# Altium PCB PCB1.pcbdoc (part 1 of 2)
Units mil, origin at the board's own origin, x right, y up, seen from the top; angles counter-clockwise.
Board outline 3543.4 x 3543.1 mil, 4 copper layers (Top Layer, Inner1, Inner2, Bottom Layer), stack 62.5 mil thick; 107 components, 108 nets, 595 pads, 260 vias.
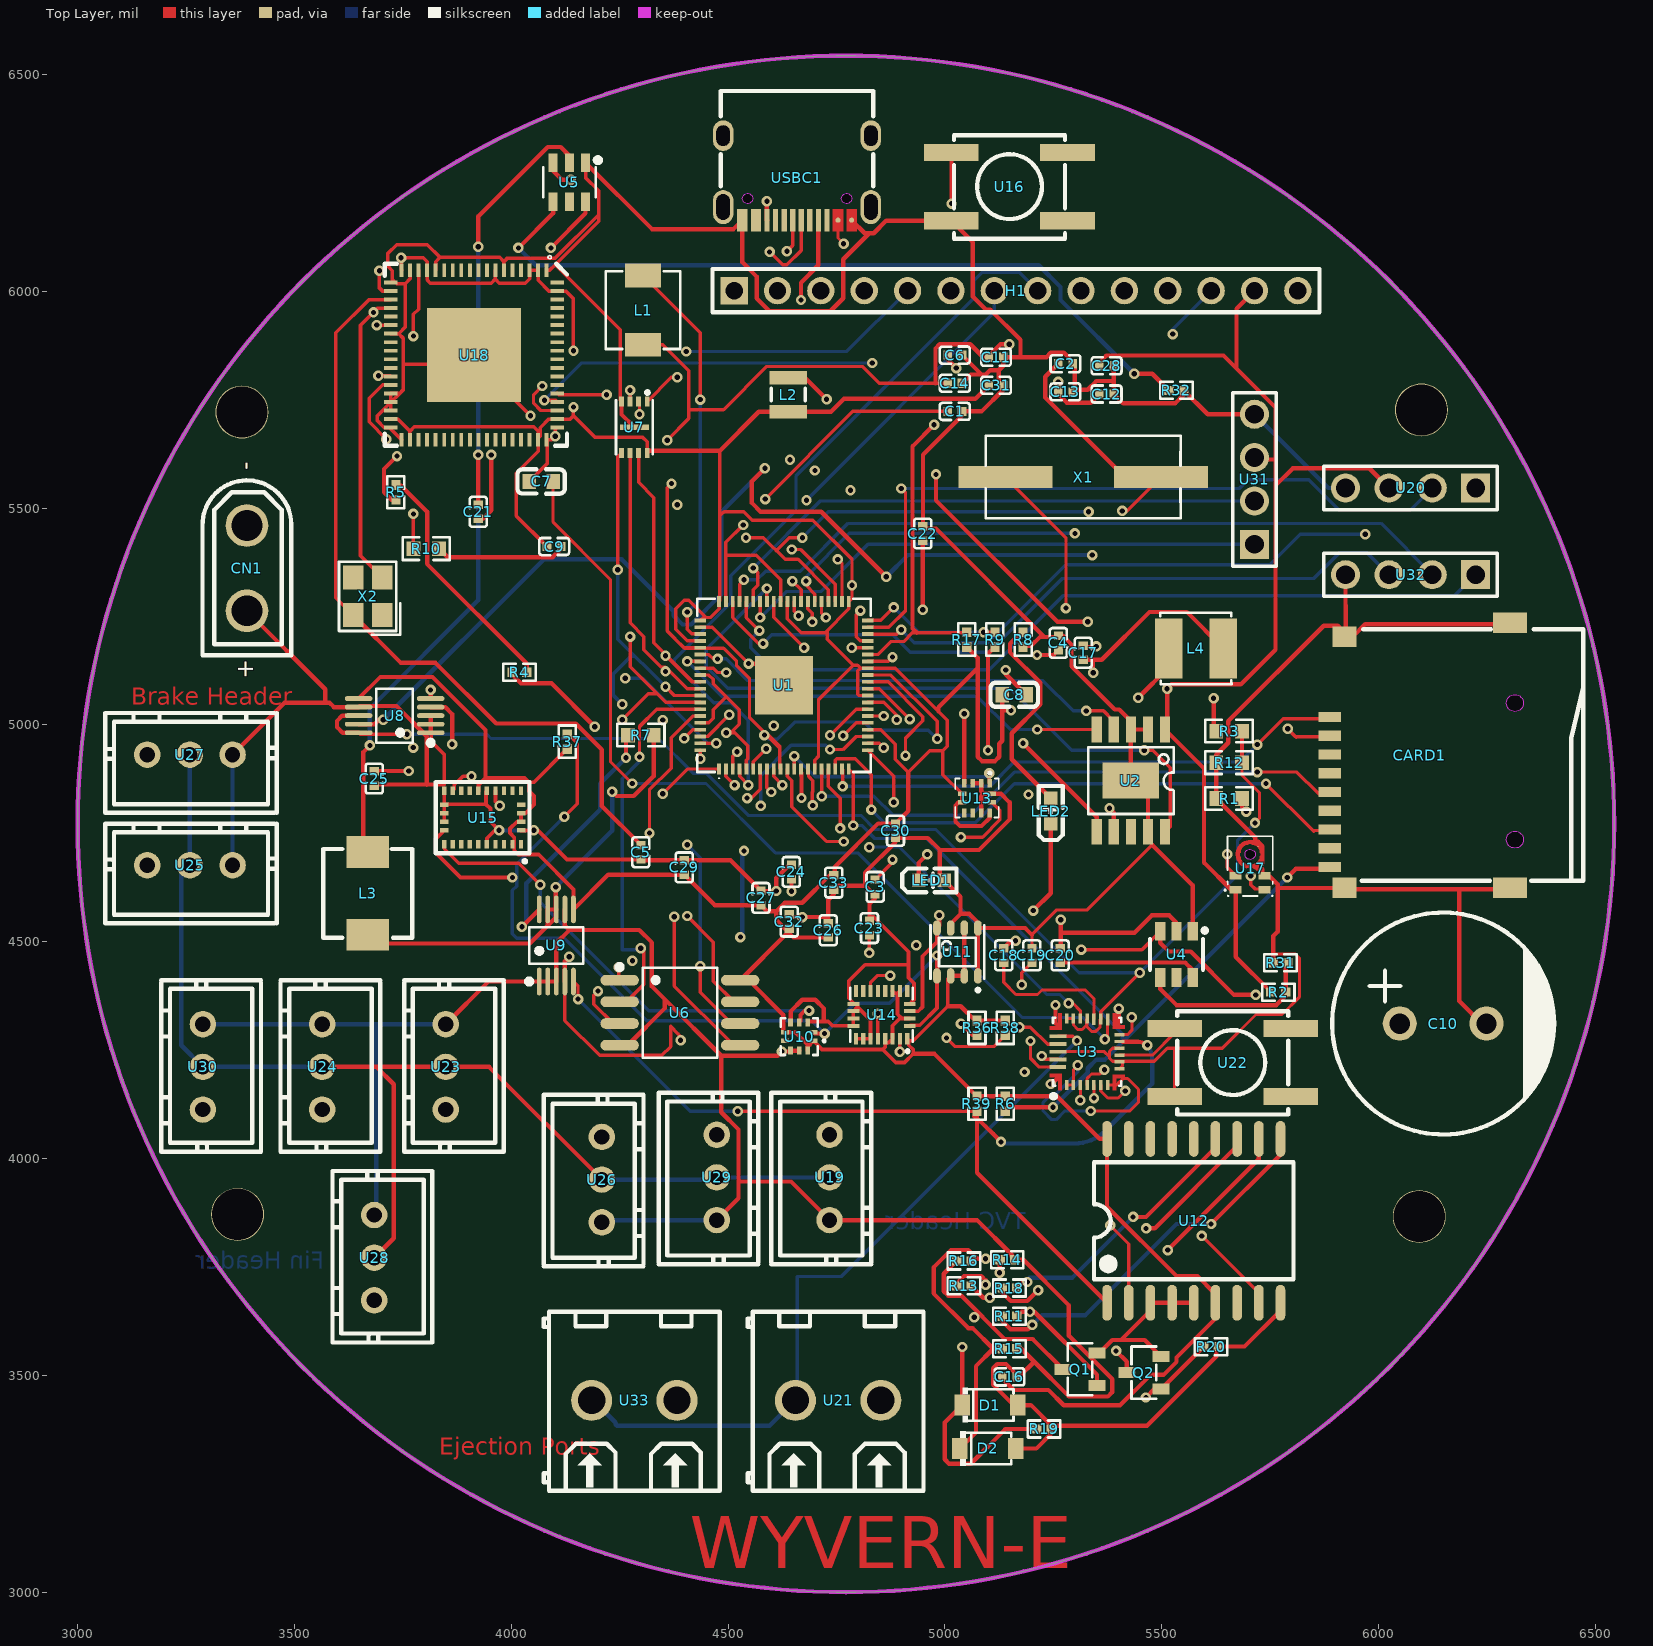
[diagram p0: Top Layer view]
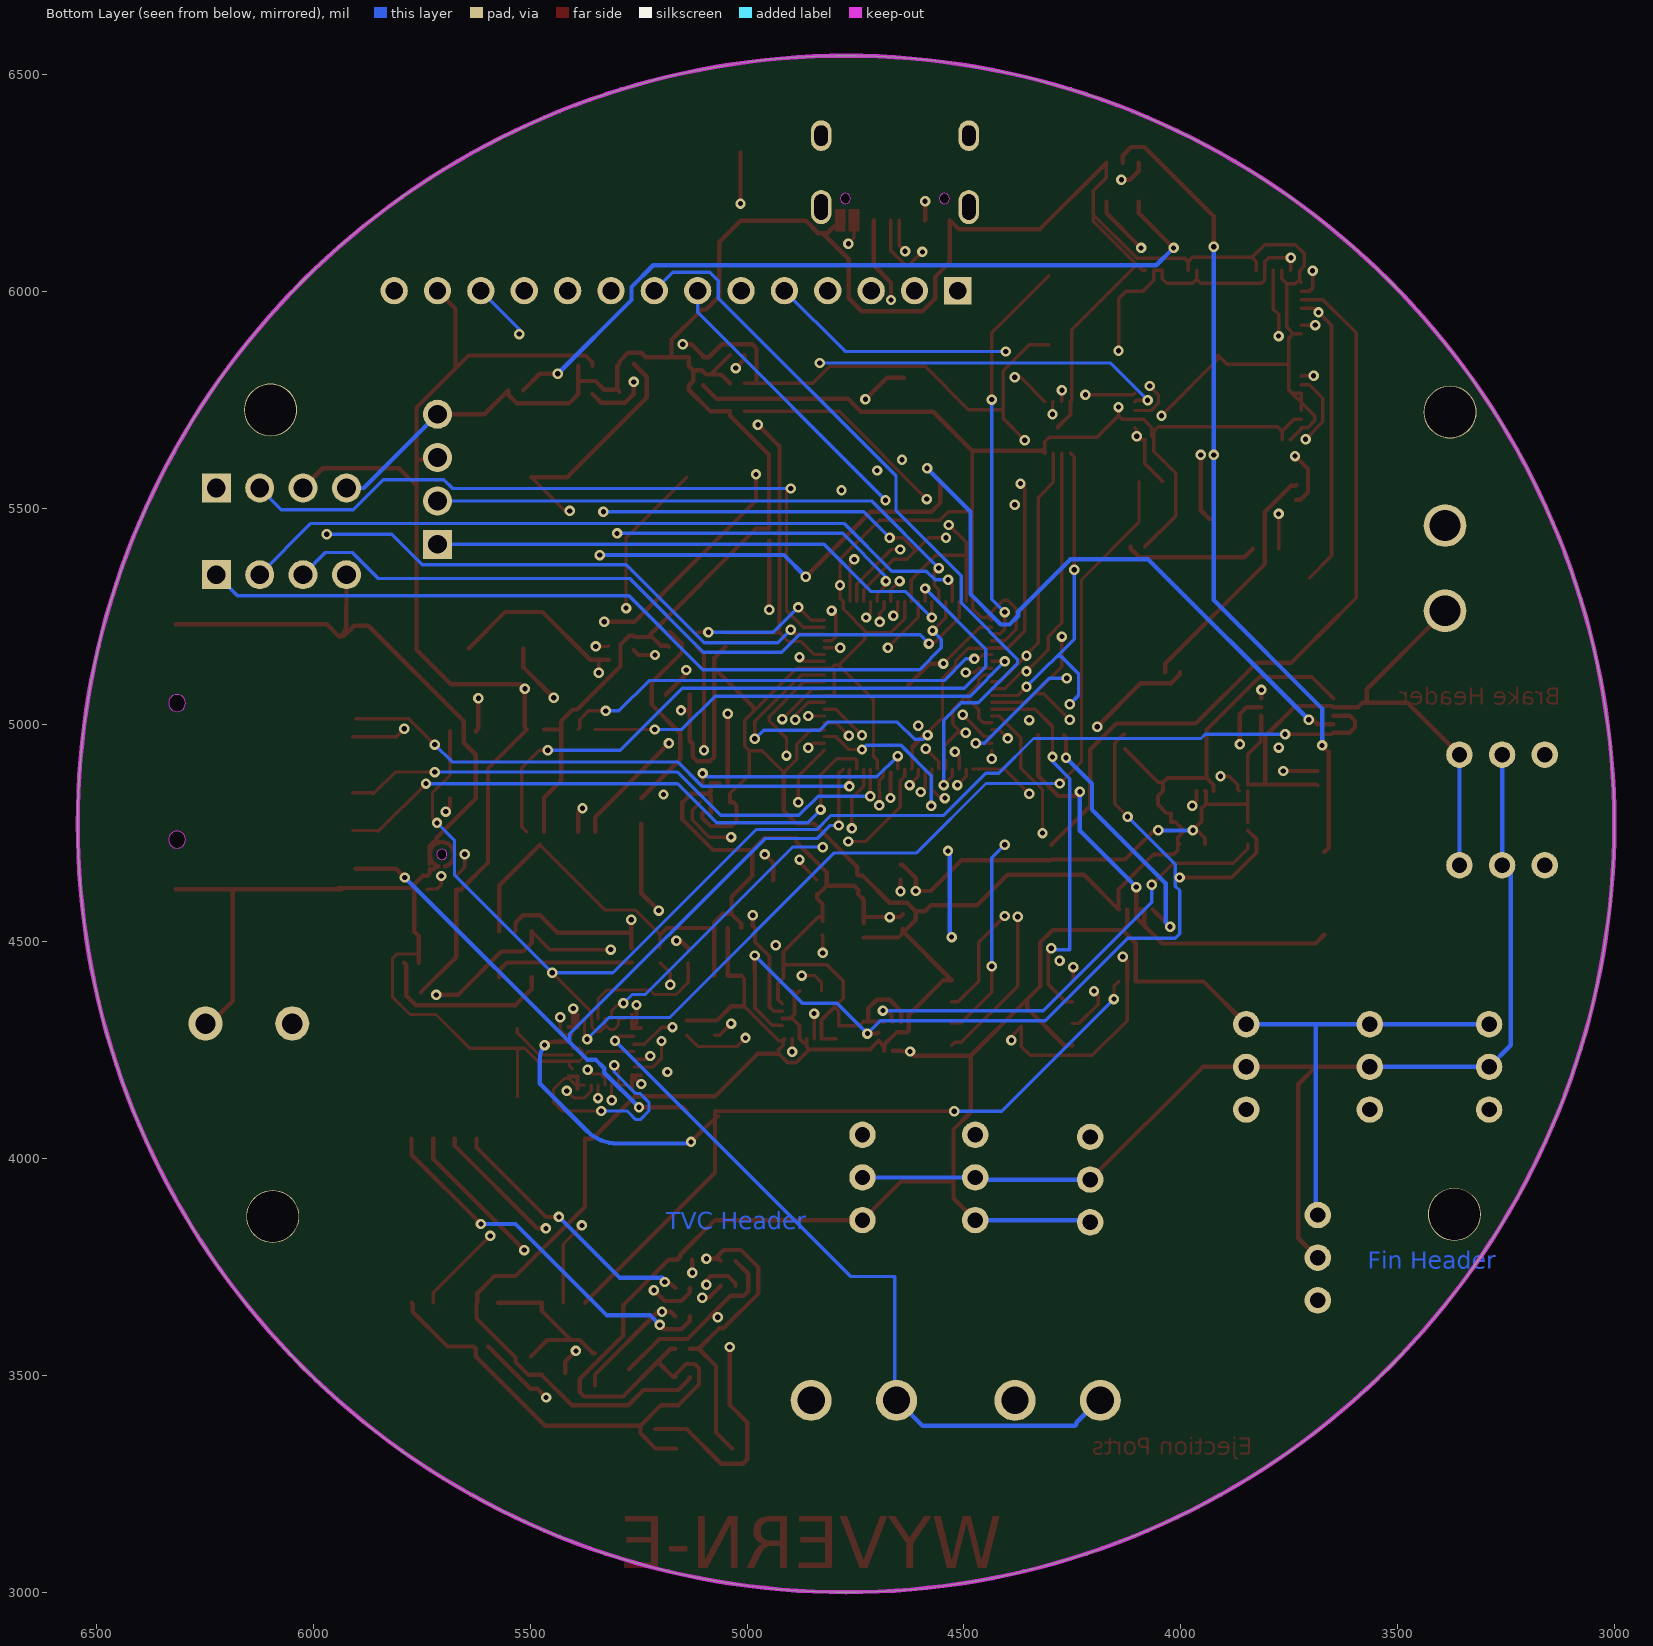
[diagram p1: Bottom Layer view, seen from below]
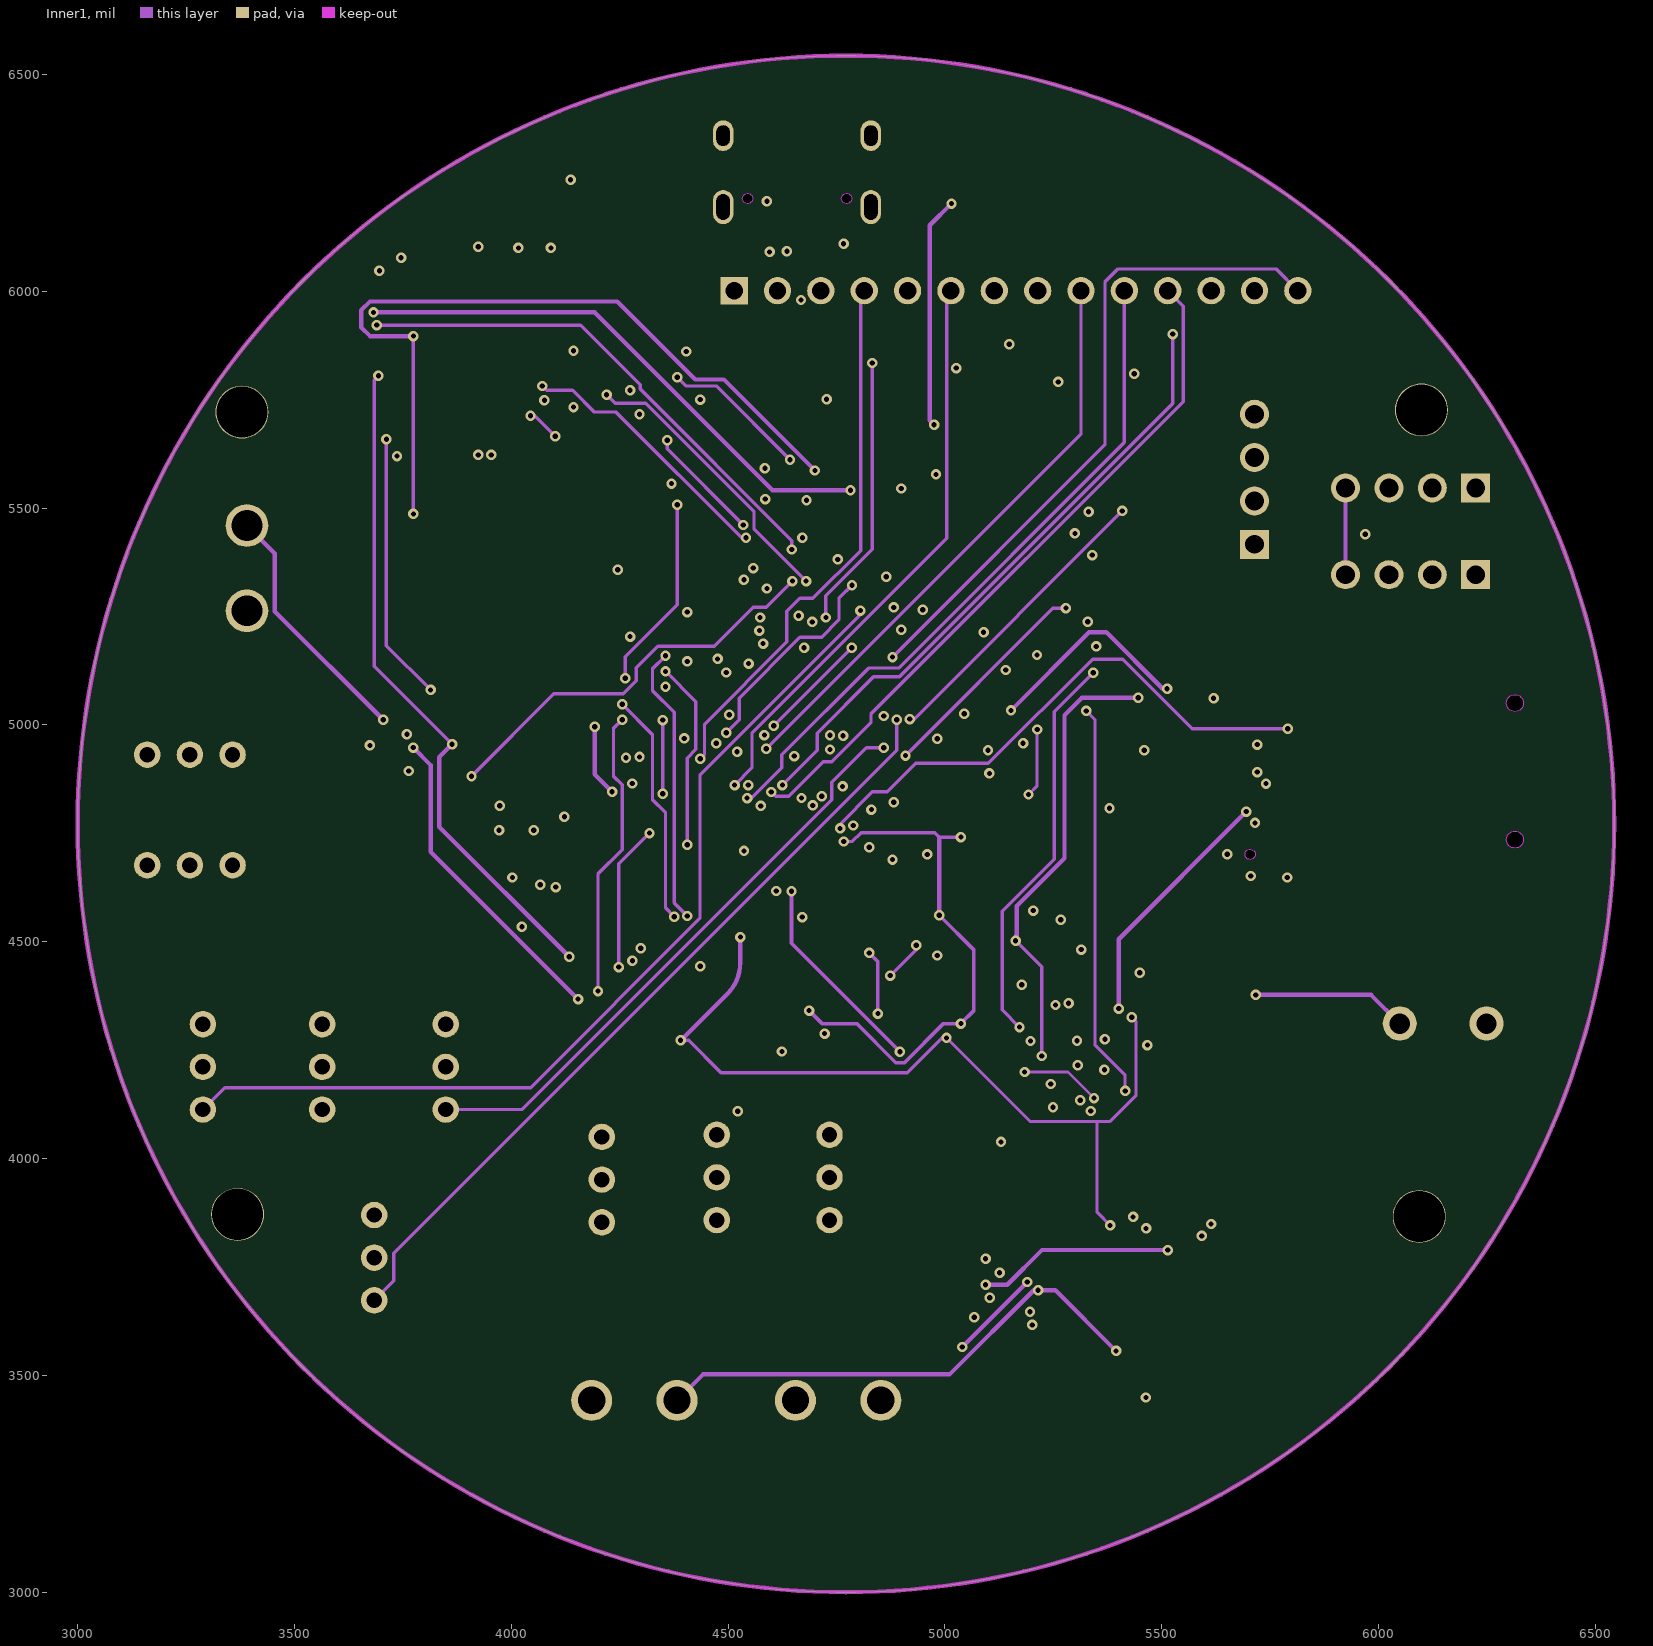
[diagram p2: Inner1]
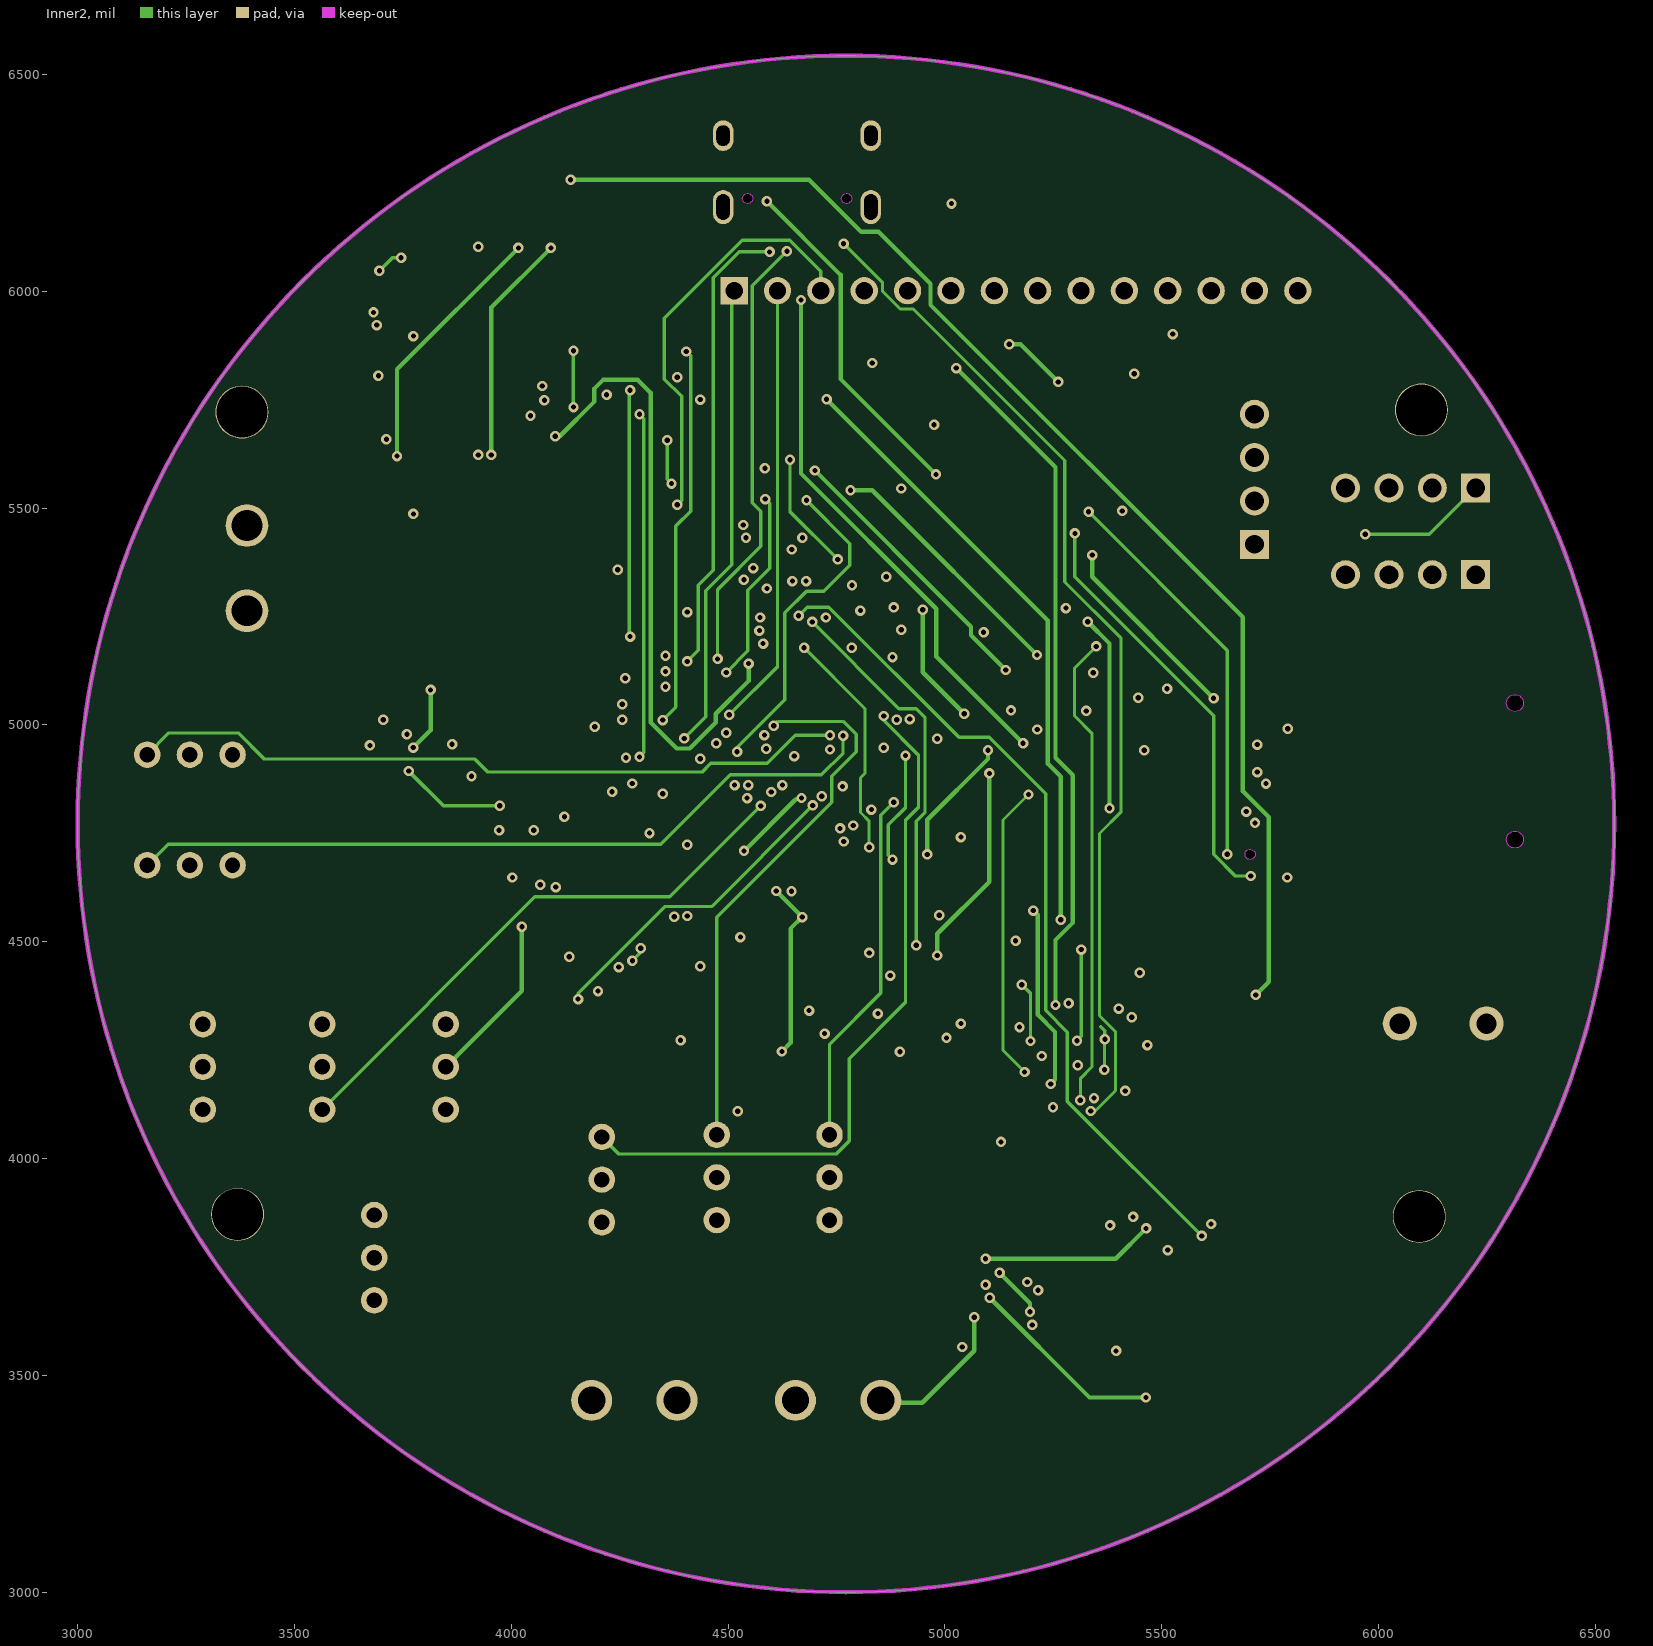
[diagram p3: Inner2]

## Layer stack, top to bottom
Top Layer: signal copper 1.4
Dielectric1: surface 8.3, 7628 RC49% 8.6mil, Dk 0
Inner1: signal copper 0.6
Dielectric2: surface 41.9, 1.1mm H/HOZ Copper, Dk 0
Inner2: signal copper 0.6
Dielectric3: surface 8.3, 7628 RC49% 8.6mil, Dk 0
Bottom Layer: signal copper 1.4

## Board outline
6543.3,4771.7 ccw(c4771.7,4771.7) 3000,4771.7 ccw(c4771.7,4771.7)

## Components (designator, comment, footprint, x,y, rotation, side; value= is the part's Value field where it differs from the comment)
C1 "100nF" C0402#1 5022.6,5723 r0 top
C2 "18pF" C0402#1 5277.6,5833.1 r0 top
C3 "18pF" C0402#2 4838.7,4626.5 r270 top
C4 "18pF" C0402#3 5261.6,5189.1 r90 top
C5 "18pF" C0402#2 4298.7,4706.5 r270 top
C6 "1nF" C0402#1 5022.6,5853 r0 top
C7 "4.7uF" C0603#1 4068.7,5561.5 r180 top
C8 "150pF" C0603#2 5159.8,5069.5 r0 top
C9 "5.6nF" C0402#2 4098.7,5411.5 r0 top
C10 "2200uF" CAP-TH_BD13.0-P5.00-D1.2-FD 6148.7,4311.5 r0 top
C11 "100nF" C0402#1 5117.6,5848.1 r0 top
C12 "100nF" C0402#1 5372.6,5763.1 r0 top
C13 "100nF" C0402#1 5277.6,5768 r0 top
C14 "100nF" C0402#1 5022.6,5788 r0 top
C16 "100nF" C0402#2 5148.7,3496.5 r0 top
C17 "100nF" C0402#2 5318.7,5166.5 r270 top
C18 "100nF" C0402#3 5135.5,4468.7 r90 top
C19 "100nF" C0402#3 5200.5,4468.7 r90 top
C20 "100nF" C0402#3 5265.6,4468.7 r90 top
C21 "100nF" C0402#2 3923.7,5491.5 r90 top
C22 "100nF" C0402#2 4948.7,5441.5 r90 top
C23 "100nF" C0402#3 4825.8,4531.6 r90 top
C24 "100nF" C0402#3 4645.8,4661.1 r90 top
C25 "100nF" C0402#2 3683.7,4876.5 r270 top
C26 "100nF" C0402#3 4730.8,4526.6 r90 top
C27 "100nF" C0402#3 4575.8,4601.1 r90 top
C28 "100nF" C0402#1 5372.6,5828.2 r0 top
C29 "100nF" C0402#2 4398.7,4671.5 r90 top
C30 "100nF" C0402#1 4885.9,4756.1 r270 top
C31 "100nF" C0402#1 5117.6,5783.1 r0 top
C32 "100nF" C0402#3 4640.7,4546.6 r90 top
C33 "100nF" C0402#2 4743.7,4636.5 r270 top
CARD1 "TF-01A" TF-SMD_TF-01A 6095.1,4930.4 r90 top
CN1 "XT30UPB-M" CONN-TH_XT30UPB-M 3390.2,5361.5 r270 top
D1 "BZT52C3V3" SOD-123_L2.7-W1.6-LS3.7-RD 5103.7,3431.5 r0 top
D2 "BZT52C3V3" SOD-123_L2.7-W1.6-LS3.7-RD 5098.7,3331.5 r0 top
H1 "2011-1X14G00SB" HDR-TH_14P-P2.54-V-M_4 5163.7,6001.5 r0 top
L1 "1uH" IND-SMD_L4.4-W4.2 4303.7,5956.5 r90 top
L2 "2.2uH" IND-SMD_L2.5-W2.0_MHCHL2520 4638.7,5761.5 r270 top
L3 "2.2uH" IND-SMD_L5.5-W5.2_NBMC0530N 3668.7,4611.5 r270 top
L4 "3.3uH" IND-SMD_L4.0-W4.0 5578.7,5176.5 r180 top
LED1 "KT-0603R" LED-SMD_L1.6-W0.8-R-RD 4968.7,4641.5 r0 top
LED2 "KT-0603R" LED-SMD_L1.6-W0.8-R-RD 5243.7,4801.5 r90 top
Q1 "AO3400A" SOT-23-3_L2.9-W1.3-P1.90-LS2.4-BR#1 5311.4,3514 r0 top
Q2 "AO3400A" SOT-23-3_L2.9-W1.3-P1.90-LS2.4-BR#2 5458.7,3506.5 r0 top
R1 "NCP18XH103F03RB" R0603#1 5655.2,4830.3 r180 top
R2 "330kΩ" R0402#1 5768.8,4383.9 r0 top
R3 "10mΩ" R0603#1 5655.2,4985.7 r180 top
R4 "680kΩ" R0402#1 4018.7,5121.5 r0 top
R5 "68kΩ" R0402#1 3733.7,5536.5 r270 top
R6 "20kΩ" R0402#2 5138.7,4126.4 r90 top
R7 "10mΩ" R0603#2 4298.7,4976.5 r0 top
R8 "100kΩ" R0402#2 5180,5197 r270 top
R9 "330Ω" R0402#2 5115.1,5197 r270 top
R10 "4.3kΩ" R0603#2 3803.7,5406.5 r0 top
R11 "1kΩ" R0402#1 5148.7,3636.5 r0 top
R12 "100Ω" R0603#1 5655.2,4913 r180 top
R13 "1kΩ" R0402#1 5043.7,3706.5 r0 top
R14 "10kΩ" R0402#1 5143.7,3766.5 r0 top
R15 "10kΩ" R0402#1 5148.7,3561.5 r0 top
R16 "33kΩ" R0402#2 5043.7,3763.9 r0 top
R17 "10kΩ" R0402#2 5050.1,5197 r270 top
R18 "33kΩ" R0402#1 5148.7,3701.5 r0 top
R19 "10kΩ" R0402#1 5228.7,3376.5 r0 top
R20 "10kΩ" R0402#1 5613.7,3566.5 r0 top
R31 "100kΩ" R0402#1 5773.7,4451.5 r180 top
R32 "100kΩ" R0402#1 5533.7,5771.5 r0 top
R36 "4.7kΩ" R0402#2 5073.8,4301.4 r90 top
R37 "4.7kΩ" R0402#1 4128.7,4961.5 r270 top
R38 "4.7kΩ" R0402#2 5138.8,4301.4 r90 top
R39 "4.7kΩ" R0402#2 5073.7,4126.4 r90 top
U1 "RP2350B" QFN-80_L10.0-W10.0-P0.40-TL-EP3.4 4628.7,5091.5 r90 top
U2 "CH224K" ESSOP-10_L4.9-W3.9-P1.0-LS6.0-TL-EP 5428.7,4871.5 r180 top
U3 "BQ25798RQMR" QFN-29_L4.0-W4.0-P0.40-TL-BQ25792RQMR 5328.7,4246.5 r90 top
U4 "TPS563201DDCR" SOT-23-6_L2.9-W1.6-P0.95-LS2.8-BR 5533.9,4471 r90 top
U5 "TPS54202DDCR" SOT-23-6_L2.9-W1.6-P0.95-LS2.8-BL 4133.7,6251.5 r180 top
U6 "W25Q32JVSSIQ" SOIC-8_L5.3-W5.3-P1.27-LS8.0-BL 4388.7,4336.5 r270 top
U7 "APS6404L-3SQR-ZR" USON-8_L3.0-W2.0-P0.50-BL-EP 4283.7,5686.5 r180 top
U8 "INA226AIDGSR" MSOP-10_L3.0-W3.0-P0.50-LS5.0-BL 3730.8,5021.5 r90 top
U9 "INA226AIDGSR" MSOP-10_L3.0-W3.0-P0.50-LS5.0-BL 4103.7,4491.5 r0 top
U10 "LPS22HBTR" HLGA-10L_LPS22HBTR 4663.7,4281.5 r180 top
U11 "BME680" LGA-8_L3.0-W3.0-P0.80-TR 5028.7,4476.5 r270 top
U12 "MCP23008-E/SO" SOIC-18_L11.6-W7.5-P1.27-LS10.3-BL 5573.7,3856.5 r0 top
U13 "LIS3MDLTR" LGA-12_L2.0-W2.0-P0.50-BL 5073.7,4831.5 r180 top
U14 "LSM9DS1TR" LGA-24_L3.5-W3.0-P0.43-TL 4853.7,4331.5 r180 top
U15 "BNO055" LGA-28_L5.2-W3.8-P0.50-BL 3933.7,4786.5 r90 top
U16 "EVQ-Q2P02W" SW-SMD_4P-L6.5-W6.0-P4.00-LS6.6-TL 5148.7,6241.5 r0 top
U17 "IM63D135AXTMA1" MIC-SMD_5P-L3.5-W2.7_IM66D130AXTMA1 5703.7,4671.5 r0 top
U18 "ADAU1450WBCPZ-RL" LFCSP-72_L10.0-W9.8-P0.50-LS10.2-TL-EP5.5 3914.1,5853.1 r270 top
U19 "B3B-XH-A(LF)(SN)" CONN-TH_3P-P2.50_A2501WV2-3P 4733.7,3956.5 r270 top
U20 "2.54-1*4" HDR-TH_4P-P2.54-V-M-1 6073.7,5546.5 r180 top
U21 "KF128-5.0-2P" CONN-TH_P5.00_KF128-5.0-2P 4753.5,3442.4 r0 top
U22 "EVQ-Q2P02W" SW-SMD_4P-L6.5-W6.0-P4.00-LS6.6-TL 5663.7,4221.5 r0 top
U23 "B3B-XH-A(LF)(SN)" CONN-TH_3P-P2.50_A2501WV2-3P 3848.7,4211.5 r90 top
U24 "B3B-XH-A(LF)(SN)" CONN-TH_3P-P2.50_A2501WV2-3P 3563.7,4211.5 r90 top
U25 "B3B-XH-A(LF)(SN)" CONN-TH_3P-P2.50_A2501WV2-3P 3258.7,4676.5 r0 top
U26 "B3B-XH-A(LF)(SN)" CONN-TH_3P-P2.50_A2501WV2-3P 4208.7,3951.5 r270 top
U27 "B3B-XH-A(LF)(SN)" CONN-TH_3P-P2.50_A2501WV2-3P 3258.7,4931.5 r0 top
U28 "B3B-XH-A(LF)(SN)" CONN-TH_3P-P2.50_A2501WV2-3P 3683.7,3771.5 r90 top
U29 "B3B-XH-A(LF)(SN)" CONN-TH_3P-P2.50_A2501WV2-3P 4473.7,3956.5 r270 top
U30 "B3B-XH-A(LF)(SN)" CONN-TH_3P-P2.50_A2501WV2-3P 3288.7,4211.5 r90 top
U31 "2.54-1*4" HDR-TH_4P-P2.54-V-M-1 5713.7,5566.5 r90 top
U32 "2.54-1*4" HDR-TH_4P-P2.54-V-M-1 6073.7,5346.5 r180 top
U33 "KF128-5.0-2P" CONN-TH_P5.00_KF128-5.0-2P 4283.5,3442.4 r0 top
USBC1 "TYPE-C-31-M-12" USB-C_SMD-TYPE-C-31-M-12_1 4658.7,6261.5 r180 top
X1 "12MHz" HC-49S_L11.4-W4.8 5318.7,5571.5 r0 top
X2 "-" CRYSTAL-SMD_4P-L3.2-W2.5-BL 3668.7,5296.5 r90 top

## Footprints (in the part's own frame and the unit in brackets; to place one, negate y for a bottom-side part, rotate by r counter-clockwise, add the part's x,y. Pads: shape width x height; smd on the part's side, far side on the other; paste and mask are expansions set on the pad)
C0402#1 [mil]
  rect 19.7x21.3 smd: 1(-16.5,0) 2(16.6,0)
  silkscreen extent -34,-20 34,20
C0402#2 [mil]
  rect 19.7x21.3 smd: 1(-16.5,0) 2(16.5,0)
  silkscreen extent -34,-20 34,20
C0402#3 [mil]
  rect 19.7x21.3 smd: 1(-16.6,0) 2(16.5,0)
  silkscreen extent -34,-20 34,20
C0603#1 [mil]
  rect 31.5x35.4 smd: 1(-27.6,0) 2(27.6,0)
  silkscreen extent -55,-28 55,28
C0603#2 [mil]
  rect 31.5x35.4 smd: 1(-27.6,0) 2(27.5,0)
  silkscreen extent -55,-28 55,28
CAP-TH_BD13.0-P5.00-D1.2-FD [mil]
  round 78.7 hole 47.2: 1(-100,0) 2(100,0)
  silkscreen extent -256,-256 256,256
CONN-TH_3P-P2.50_A2501WV2-3P [mil]
  round 61 hole 35.4: 1(-98.4,0) 2(0,0) 3(98.4,0)
  silkscreen extent -196,-134 200,96
CONN-TH_P5.00_KF128-5.0-2P [mil]
  round 94.5 hole 63: 1(-98.4,0) 2(98.5,0)
  silkscreen extent -209,-209 197,205
CONN-TH_XT30UPB-M [mil]
  round 98.4 hole 70.9: 1(-98.4,0) 2(98.4,0)
  silkscreen extent -202,-102 201,102
CRYSTAL-SMD_4P-L3.2-W2.5-BL [mil]
  rect 55.1x47.2 smd: 1(-43.3,-33.5) 2(43.3,-33.5) 3(43.3,33.5) 4(-43.3,33.5)
  silkscreen extent -89,-75 80,66
ESSOP-10_L4.9-W3.9-P1.0-LS6.0-TL-EP [mil]
  rect 23.6x59.1 smd paste+0 mask+2: 1(-78.7,-118.1) 2(-39.4,-118.1) 3(0,-118.1) 4(39.4,-118.1) 5(78.7,-118.1) 6(78.7,118.1) 7(39.4,118.1) 8(0,118.1) 9(-39.4,118.1) 10(-78.7,118.1)
  rect 129.9x82.7 smd paste+0 mask+2: 11(0,0)
  silkscreen extent -98,-77 98,77
HC-49S_L11.4-W4.8 [mil]
  rect 216.5x51.2 smd: 1(-179.2,0) 2(179.3,0)
  silkscreen extent -225,-95 225,95
HDR-TH_4P-P2.54-V-M-1 [mil]
  rect 66.9x66.9 hole 43.3: 1(-150,0)
  round 66.9 hole 43.3: 2(-50,0) 3(50,0) 4(150,0)
  silkscreen extent -200,-50 200,50
HDR-TH_14P-P2.54-V-M_4 [mil]
  rect 63x63 hole 40.2: 1(-650,0)
  round 63 hole 40.2: 2(-550,0) 3(-450,0) 4(-350,0) 5(-250,0) 6(-150,0) 7(-50,0) 8(50,0) 9(150,0) 10(250,0) 11(350,0) 12(450,0) 13(550,0) 14(650,0)
  silkscreen extent -700,-50 700,50
HLGA-10L_LPS22HBTR [mil]
  rect 18.3x11 smd: 1(-32.8,10) 2(-32.8,-9.6) 6(32.8,-9.6) 7(32.8,10)
  rect 11x18.3 smd: 3(-19.7,-32.6) 4(0,-32.6) 5(19.7,-32.6) 8(19.7,32.6) 9(0,32.6) 10(-19.7,32.6)
  silkscreen extent -60,-42 42,43
IND-SMD_L2.5-W2.0_MHCHL2520 [mil]
  rect 31.5x86.6 smd: 1(-39.4,0) 2(39.4,0)
  silkscreen extent -15,-39 15,39
IND-SMD_L4.0-W4.0 [mil]
  rect 63x137.8 smd: 1(-63,0) 2(63,0)
  silkscreen extent -82,-83 82,83
IND-SMD_L4.4-W4.2 [mil]
  rect 55.1x83.5 smd: 1(79.8,0) 2(-79.8,0)
  silkscreen extent -90,-86 90,86
IND-SMD_L5.5-W5.2_NBMC0530N [mil]
  rect 72.8x98.4 smd: 1(-95.5,0) 2(95.5,0)
  silkscreen extent -102,-102 102,102
LED-SMD_L1.6-W0.8-R-RD [mil]
  rect 31.5x31.5 smd: 1(29.5,0) 2(-29.5,0)
  silkscreen extent -67,-28 58,28
LFCSP-72_L10.0-W9.8-P0.50-LS10.2-TL-EP5.5 [mil]
  rect 31.5x9.1 smd paste-3937 mask+2: 1(-195.5,167.3) 2(-195.5,147.6) 3(-195.5,127.9) 4(-195.5,108.2) 5(-195.5,88.5) 6(-195.5,68.9) 7(-195.5,49.2) 8(-195.5,29.5) 9(-195.5,9.8) 10(-195.5,-9.9) 11(-195.5,-29.6) 12(-195.5,-49.3) 13(-195.5,-68.9) 14(-195.5,-88.6) 15(-195.5,-108.3) 16(-195.5,-128) 17(-195.5,-147.7) 18(-195.5,-167.4) 37(195.5,-167.4) 38(195.5,-147.7) 39(195.5,-128) 40(195.5,-108.3) 41(195.5,-88.6) 42(195.5,-68.9) 43(195.5,-49.3) 44(195.5,-29.6) 45(195.5,-9.9) 46(195.5,9.8) 47(195.5,29.5) 48(195.5,49.2) 49(195.5,68.9) 50(195.5,88.5) 51(195.5,108.2) 52(195.5,127.9) 53(195.5,147.6) 54(195.5,167.3)
  rect 9.1x31.5 smd paste-3937 mask+2: 19(-167.3,-192.2) 20(-147.6,-192.2) 21(-128,-192.2) 22(-108.3,-192.2) 23(-88.6,-192.2) 24(-68.9,-192.2) 25(-49.2,-192.2) 26(-29.5,-192.2) 27(-9.9,-192.2) 28(9.8,-192.2) 29(29.5,-192.2) 30(49.2,-192.2) 31(68.9,-192.2) 32(88.6,-192.2) 33(108.3,-192.2) 34(127.9,-192.2) 35(147.6,-192.2) 36(167.3,-192.2) 55(167.3,192.1) 56(147.6,192.1) 57(127.9,192.1) 58(108.3,192.1) 59(88.6,192.1) 60(68.9,192.1) 61(49.2,192.1) 62(29.5,192.1) 63(9.8,192.1) 64(-9.9,192.1) 65(-29.5,192.1) 66(-49.2,192.1) 67(-68.9,192.1) 68(-88.6,192.1) 69(-108.3,192.1) 70(-128,192.1) 71(-147.6,192.1) 72(-167.3,192.1)
  rect 216.5x216.5 smd paste-3937 mask+2: 73(0,0)
  silkscreen extent -230,-206 209,214
LGA-8_L3.0-W3.0-P0.80-TR [mil]
  oval 35.4x17.6 smd: 1(55.1,47.2) 2(55.1,15.8) 3(55.1,-15.7) 4(55.1,-47.2) 5(-55.1,-47.2) 6(-55.1,-15.7) 7(-55.1,15.8) 8(-55.1,47.2)
  silkscreen extent -62,-62 92,62
LGA-12_L2.0-W2.0-P0.50-BL [mil]
  rect 11x19.7 smd: 1(-29.5,-34.4) 2(-9.8,-34.4) 3(9.8,-34.4) 4(29.5,-34.4) 7(29.5,34.5) 8(9.8,34.5) 9(-9.8,34.5) 10(-29.5,34.5)
  rect 19.7x11 smd: 5(34.4,-9.8) 6(34.4,9.8) 11(-34.5,9.8) 12(-34.5,-9.8)
  silkscreen extent -50,-60 50,45
LGA-24_L3.5-W3.0-P0.43-TL [mil]
  rect 9.5x27.6 smd: 1(-59.3,55.1) 6(-59.3,-55.1) 7(-42.3,-55.1) 8(-25.4,-55.1) 9(-8.5,-55.1) 10(8.5,-55.1) 11(25.4,-55.1) 12(42.3,-55.1) 13(59.2,-55.1) 18(59.2,55.1) 19(42.3,55.1) 20(25.4,55.1) 21(8.5,55.1) 22(-8.5,55.1) 23(-25.4,55.1) 24(-42.3,55.1)
  rect 27.6x9.5 smd: 2(-65,25.4) 3(-65,8.5) 4(-65,-8.5) 5(-65,-25.4) 14(65,-25.4) 15(65,-8.5) 16(65,8.5) 17(65,25.4)
  silkscreen extent -72,-62 72,87
LGA-28_L5.2-W3.8-P0.50-BL [mil]
  rect 19.7x9.8 smd: 1(-61.5,-88.6) 6(61.5,-88.6) 7(61.5,-68.9) 8(61.5,-49.2) 9(61.5,-29.5) 10(61.5,-9.8) 11(61.5,9.8) 12(61.5,29.5) 13(61.5,49.2) 14(61.5,68.9) 15(61.5,88.6) 20(-61.5,88.6) 21(-61.5,68.9) 22(-61.5,49.2) 23(-61.5,29.5) 24(-61.5,9.8) 25(-61.5,-9.8) 26(-61.5,-29.5) 27(-61.5,-49.2) 28(-61.5,-68.9)
  rect 9.8x19.7 smd: 2(-29.5,-88.6) 3(-9.9,-88.6) 4(9.8,-88.6) 5(29.5,-88.6) 16(29.5,88.6) 17(9.8,88.6) 18(-9.9,88.6) 19(-29.5,88.6)
  silkscreen extent -105,-108 82,108
MIC-SMD_5P-L3.5-W2.7_IM66D130AXTMA1 [mil]
  rect 27.6x17.7 smd paste+0 mask+2: 1(-33.5,-51.7) 2(-33.5,-19.3) 3(33.5,-51.7) 4(33.5,-19.3)
  round 1.6 smd: 5(-18,10.8) 5(-17.6,48.7) 5(18,10.8) 5(18.4,48)
  Top Layer region: 22.6,33.8 22.6,35 22.5,36.3 22.3,37.5 22,38.8 21.6,40 21.1,41.1 20.6,42.3 19.9,43.4 19.3,44.4 18.5,45.4 17.7,46.4 16.8,47.3 15.8,48.1 14.8,48.9 13.7,49.6 12.6,50.2 11.5,50.7 10.3,51.2 9.1,51.6 7.9,51.9 6.7,52.1 5.4,52.2 4.1,52.3 3.7,52.3 3.7,59.4 4.5,59.4 6,59.3 7.4,59.2 8.8,59 10.2,58.7 11.6,58.4 13,57.9 14.3,57.4 15.6,56.8 16.9,56.2 18.1,55.4 19.3,54.6 20.5,53.8 21.6,52.9 22.6,51.9 23.6,50.8 24.5,49.7 25.4,48.6 26.2,47.4 26.9,46.1 27.6,44.9 28.2,43.6 28.7,42.2 29.1,40.9 29.5,39.5 29.8,38.1 30,36.6 30.1,35.2 30.1,33.8 29.3,33.8
  Top Layer region: -3.4,53 -4.7,53 -5.9,52.8 -7.2,52.6 -8.4,52.3 -9.6,51.9 -10.8,51.5 -11.9,50.9 -13,50.3 -14.1,49.6 -15.1,48.9 -16,48 -16.9,47.1 -17.7,46.2 -18.5,45.2 -19.2,44.1 -19.8,43 -20.4,41.9 -20.8,40.7 -21.2,39.5 -21.5,38.3 -21.7,37 -21.8,35.8 -21.9,34.5 -21.9,34.1 -29,34.1 -29,34.9 -28.9,36.3 -28.8,37.8 -28.6,39.2 -28.3,40.6 -28,42 -27.5,43.4 -27,44.7 -26.4,46 -25.8,47.3 -25.1,48.5 -24.3,49.7 -23.4,50.9 -22.5,52 -21.5,53 -20.4,54 -19.3,54.9 -18.2,55.8 -17,56.6 -15.8,57.3 -14.5,58 -13.2,58.5 -11.8,59.1 -10.5,59.5 -9.1,59.9 -7.7,60.1 -6.3,60.3 -4.8,60.5 -3.4,60.5 -3.4,59.7
  Top Layer region: -22.2,25 -22.2,23.8 -22.1,22.5 -21.9,21.3 -21.6,20 -21.2,18.8 -20.7,17.6 -20.2,16.5 -19.5,15.4 -18.9,14.4 -18.1,13.3 -17.3,12.4 -16.4,11.5 -15.4,10.7 -14.4,9.9 -13.4,9.2 -12.3,8.6 -11.1,8 -9.9,7.6 -8.7,7.2 -7.5,6.9 -6.3,6.7 -5,6.6 -3.7,6.5 -3.3,6.5 -3.3,-0.6 -4.1,-0.6 -5.6,-0.5 -7,-0.4 -8.4,-0.2 -9.8,0.1 -11.2,0.4 -12.6,0.9 -13.9,1.4 -15.2,2 -16.5,2.6 -17.7,3.4 -18.9,4.2 -20.1,5 -21.2,5.9 -22.2,6.9 -23.2,8 -24.1,9.1 -25,10.2 -25.8,11.4 -26.5,12.6 -27.2,13.9 -27.8,15.2 -28.3,16.6 -28.7,17.9 -29.1,19.3 -29.4,20.7 -29.6,22.2 -29.7,23.6 -29.7,25 -28.9,25
  Top Layer region: 3.8,6.6 5,6.6 6.3,6.7 7.5,6.9 8.8,7.2 10,7.6 11.2,8.1 12.3,8.6 13.4,9.3 14.5,9.9 15.5,10.7 16.4,11.5 17.3,12.4 18.1,13.4 18.9,14.4 19.6,15.4 20.2,16.6 20.8,17.7 21.2,18.9 21.6,20.1 21.9,21.3 22.1,22.5 22.2,23.8 22.3,25.1 22.3,25.5 29.4,25.5 29.4,24.7 29.3,23.2 29.2,21.8 29,20.4 28.7,19 28.4,17.6 27.9,16.2 27.4,14.9 26.8,13.6 26.2,12.3 25.5,11.1 24.7,9.9 23.8,8.7 22.9,7.6 21.9,6.6 20.8,5.6 19.7,4.7 18.6,3.8 17.4,3 16.2,2.3 14.9,1.6 13.6,1 12.2,0.5 10.9,0.1 9.5,-0.3 8.1,-0.6 6.6,-0.8 5.2,-0.9 3.8,-0.9 3.8,-0.1
  Board Outline Layer lines w0.1: -11.7,28.5 -11,25.6 -9.6,23 -7.5,20.9 -5,19.3 -2.2,18.4 0.7,18.2 3.7,18.8 6.3,20 8.6,21.9 10.4,24.3 11.4,27.1 11.8,30 11.4,32.9 10.4,35.7 8.6,38.1 6.3,40 3.7,41.2 0.7,41.8 -2.2,41.6 -5,40.7 -7.5,39.1 -9.6,36.9 -11,34.3 -11.7,31.5 -11.7,28.5
  Board Outline Layer region: 11.8,30 11.4,27.1 10.4,24.3 8.6,21.9 6.3,20 3.7,18.8 0.7,18.2 -2.2,18.4 -5,19.3 -7.5,20.9 -9.6,23 -11,25.6 -11.7,28.5 -11.7,31.5 -11,34.3 -9.6,36.9 -7.5,39.1 -5,40.7 -2.2,41.6 0.7,41.8 3.7,41.2 6.3,40 8.6,38.1 10.4,35.7 11.4,32.9
  Board Outline Layer region: 11.8,30 11.4,27.1 10.4,24.3 8.6,21.9 6.3,20 3.7,18.8 0.7,18.2 -2.2,18.4 -5,19.3 -7.5,20.9 -9.6,23 -11,25.6 -11.7,28.5 -11.7,31.5 -11,34.3 -9.6,36.9 -7.5,39.1 -5,40.7 -2.2,41.6 0.7,41.8 3.7,41.2 6.3,40 8.6,38.1 10.4,35.7 11.4,32.9
  Multi-Layer board cut-out: 11.8,30 11.4,27.1 10.4,24.3 8.6,21.9 6.3,20 3.7,18.8 0.7,18.2 -2.2,18.4 -5,19.3 -7.5,20.9 -9.6,23 -11,25.6 -11.7,28.5 -11.7,31.5 -11,34.3 -9.6,36.9 -7.5,39.1 -5,40.7 -2.2,41.6 0.7,41.8 3.7,41.2 6.3,40 8.6,38.1 10.4,35.7 11.4,32.9
  silkscreen extent -60,-66 52,72
MSOP-10_L3.0-W3.0-P0.50-LS5.0-BL [mil]
  oval 11x63.8 smd: 1(-39.4,-83.1) 2(-19.7,-83.1) 3(0,-83.1) 4(19.7,-83.1) 5(39.4,-83.1) 6(39.4,83.1) 7(19.7,83.1) 8(0,83.1) 9(-19.7,83.1) 10(-39.4,83.1)
  silkscreen extent -69,-89 62,42
QFN-29_L4.0-W4.0-P0.40-TL-BQ25792RQMR [mil]
  round 0 smd: 1(-69.9,73.8) 9(-70.9,-71.9) 16(70.9,-71.9) 24(69.9,73.8)
  rect 23.6x7.9 smd: 2(-76.8,48.2) 3(-76.8,32.5) 4(-76.8,16.7) 5(-76.8,1) 6(-76.8,-14.8) 7(-76.8,-30.5) 8(-76.8,-46.3) 20(76.8,1) 21(76.8,16.7) 22(76.8,32.5) 23(76.8,48.2)
  rect 7.9x23.6 smd: 10(-39.4,-73.8) 11(-23.6,-73.8) 12(-7.9,-73.8) 13(7.9,-73.8) 14(23.6,-73.8) 15(39.4,-73.8)
  rect 27.6x7.9 smd: 17(74.8,-46.3)
  rect 25.6x7.9 smd: 18(75.8,-30.5)
  rect 26.8x7.9 smd: 19(75.2,-14.8)
  rect 8.7x39.4 smd: 25(35.4,67.9) 26(17.7,67.9) 27(0,67.9) 28(-17.7,67.9)
  rect 8.7x37.4 smd: 29(-35.4,68.9)
  Top Layer region: 88.6,-65.9 88.6,-58.1 61,-58.1 53.1,-58.1 53.1,-58.1 53.1,-65.9 53.1,-65.9 53.1,-85.6 61,-85.6 61,-65.9
  Top Layer region: -53.2,-65.9 -53.2,-58.1 -53.2,-58.1 -61,-58.1 -88.6,-58.1 -88.6,-65.9 -61,-65.9 -61,-85.6 -53.2,-85.6 -53.2,-65.9
  Top Layer region: 59,67.9 59,87.6 51.2,87.6 51.2,67.9 51.2,60 88.6,60 88.6,67.9
  Top Layer region: -51.2,67.9 -51.2,87.6 -59.1,87.6 -59.1,67.9 -88.6,67.9 -88.6,60 -51.2,60 -51.2,67.9
  silkscreen extent -108,-78 79,84
QFN-80_L10.0-W10.0-P0.40-TL-EP3.4 [mil]
  rect 26.2x8.7 smd: 1(-193.2,149.6) 2(-193.2,133.9) 3(-193.2,118.1) 4(-193.2,102.4) 5(-193.2,86.6) 6(-193.2,70.9) 7(-193.2,55.1) 8(-193.2,39.4) 9(-193.2,23.6) 10(-193.2,7.9) 11(-193.2,-7.9) 12(-193.2,-23.6) 13(-193.2,-39.4) 14(-193.2,-55.1) 15(-193.2,-70.9) 16(-193.2,-86.6) 17(-193.2,-102.4) 18(-193.2,-118.1) 19(-193.2,-133.9) 20(-193.2,-149.6) 41(193.2,-149.6) 42(193.2,-133.9) 43(193.2,-118.1) 44(193.2,-102.4) 45(193.2,-86.6) 46(193.2,-70.9) 47(193.2,-55.1) 48(193.2,-39.4) 49(193.2,-23.6) 50(193.2,-7.9) 51(193.2,7.9) 52(193.2,23.6) 53(193.2,39.4) 54(193.2,55.1) 55(193.2,70.9) 56(193.2,86.6) 57(193.2,102.4) 58(193.2,118.1) 59(193.2,133.9) 60(193.2,149.6)
  rect 8.7x26.2 smd: 21(-149.6,-193.2) 22(-133.9,-193.2) 23(-118.1,-193.2) 24(-102.4,-193.2) 25(-86.6,-193.2) 26(-70.9,-193.2) 27(-55.1,-193.2) 28(-39.4,-193.2) 29(-23.6,-193.2) 30(-7.9,-193.2) 31(7.9,-193.2) 32(23.6,-193.2) 33(39.4,-193.2) 34(55.1,-193.2) 35(70.9,-193.2) 36(86.6,-193.2) 37(102.4,-193.2) 38(118.1,-193.2) 39(133.9,-193.2) 40(149.6,-193.2) 61(149.6,193.2) 62(133.9,193.2) 63(118.1,193.2) 64(102.4,193.2) 65(86.6,193.2) 66(70.9,193.2) 67(55.1,193.2) 68(39.4,193.2) 69(23.6,193.2) 70(7.9,193.2) 71(-7.9,193.2) 72(-23.6,193.2) 73(-39.4,193.2) 74(-55.1,193.2) 75(-70.9,193.2) 76(-86.6,193.2) 77(-102.4,193.2) 78(-118.1,193.2) 79(-133.9,193.2) 80(-149.6,193.2)
  rect 133.9x133.9 smd: 81(0,0)
  silkscreen extent -215,-200 200,200
R0402#1 [mil]
  rect 22.3x21.3 smd paste-3937 mask+2: 1(-17,0) 2(17,0)
  silkscreen extent -37,-20 37,20
R0402#2 [mil]
  rect 22.3x21.3 smd paste-3937 mask+2: 1(-17,0) 2(17.1,0)
  silkscreen extent -37,-20 37,20
R0603#1 [mil]
  rect 31.8x34 smd paste-3937 mask+2: 1(-29.6,0) 2(29.7,0)
  silkscreen extent -54,-26 55,26
R0603#2 [mil]
  rect 31.8x34 smd paste-3937 mask+2: 1(-29.7,0) 2(29.7,0)
  silkscreen extent -54,-26 54,26
SOD-123_L2.7-W1.6-LS3.7-RD [mil]
  rect 35.8x48 smd: 1(-64.4,0) 2(64.4,0)
  silkscreen extent -63,-40 54,40
SOIC-8_L5.3-W5.3-P1.27-LS8.0-BL [mil]
  oval 24.8x88.6 smd: 1(-75,-139) 2(-25,-139) 3(25,-139) 4(75,-139) 5(75,139) 6(25,139) 7(-25,139) 8(-75,139)
  silkscreen extent -111,-145 104,86
SOIC-18_L11.6-W7.5-P1.27-LS10.3-BL [mil]
  oval 22x82.7 smd: 1(-200,-189) 2(-150,-189) 3(-100,-189) 4(-50,-189) 5(0,-189) 6(50,-189) 7(100,-189) 8(150,-189) 9(200,-189) 10(200,189) 11(150,189) 12(100,189) 13(50,189) 14(0,189) 15(-50,189) 16(-100,189) 17(-150,189) 18(-200,189)
  silkscreen extent -230,-135 230,135
SOT-23-3_L2.9-W1.3-P1.90-LS2.4-BR#1 [mil]
  rect 39.4x25.6 smd: 1(39.3,-37.4) 2(39.3,37.4) 3(-39.4,0)
  silkscreen extent -29,-60 28,60
SOT-23-3_L2.9-W1.3-P1.90-LS2.4-BR#2 [mil]
  rect 39.4x25.6 smd: 1(39.4,-37.4) 2(39.4,37.4) 3(-39.4,0)
  silkscreen extent -29,-60 29,60
SOT-23-6_L2.9-W1.6-P0.95-LS2.8-BL [mil]
  rect 20.9x42.2 smd: 1(-37.4,-45.2) 2(0,-45.2) 3(37.4,-45.2) 4(37.4,45.2) 5(0,45.2) 6(-37.4,45.2)
  silkscreen extent -72,-57 61,35
SOT-23-6_L2.9-W1.6-P0.95-LS2.8-BR [mil]
  rect 43.3x23.6 smd paste+0 mask+2: 1(53.2,-37.4) 2(53.2,0) 3(53.2,37.4) 4(-53.1,37.4) 5(-53.1,0) 6(-53.1,-37.4)
  silkscreen extent -35,-70 60,61
SW-SMD_4P-L6.5-W6.0-P4.00-LS6.6-TL [mil]
  rect 126x39.4 smd paste+0 mask+2: 1(-133.9,78.7) 2(133.9,78.7) 3(-133.9,-78.7) 4(133.9,-78.7)
  silkscreen extent -128,-120 128,118
TF-SMD_TF-01A [mil]
  rect 23.6x51.2 smd: 1(88.2,207.7) 2(44.9,207.7) 3(1.6,207.7) 4(-41.7,207.7) 5(-85,207.7) 6(-128.3,207.7) 7(-171.6,207.7) 8(-214.9,207.7) 9(-258.2,207.7)
  rect 47.2x55.1 smd: 10(-305.5,174.2) 13(272.5,174.2)
  rect 47.2x78.7 smd: 11(-305.5,-207.7) 12(305.6,-207.7)
  Board Outline Layer lines w0.1: -194.8,-199.5 -198.7,-199.9 -202.4,-201 -205.8,-202.8 -208.8,-205.2 -211.2,-208.2 -213,-211.6 -214.1,-215.3 -214.5,-219.2 -214.1,-223 -213,-226.7 -211.2,-230.1 -208.8,-233.1 -205.8,-235.5 -202.4,-237.4 -198.7,-238.5 -194.8,-238.8 -191,-238.5 -187.3,-237.4 -183.9,-235.5 -180.9,-233.1 -178.5,-230.1 -176.7,-226.7 -175.5,-223 -175.2,-219.2 -175.5,-215.3 -176.7,-211.6 -178.5,-208.2 -180.9,-205.2 -183.9,-202.8 -187.3,-201 -191,-199.9 -194.8,-199.5 ; 120.1,-199.5 116.3,-199.9 112.6,-201 109.2,-202.8 106.2,-205.2 103.8,-208.2 101.9,-211.6 100.8,-215.3 100.4,-219.2 100.8,-223 101.9,-226.7 103.8,-230.1 106.2,-233.1 109.2,-235.5 112.6,-237.4 116.3,-238.5 120.1,-238.8 124,-238.5 127.7,-237.4 131.1,-235.5 134,-233.1 136.5,-230.1 138.3,-226.7 139.4,-223 139.8,-219.2 139.4,-215.3 138.3,-211.6 136.5,-208.2 134,-205.2 131.1,-202.8 127.7,-201 124,-199.9 120.1,-199.5
  Board Outline Layer region: -175.2,-219.2 -175.5,-223 -176.7,-226.7 -178.5,-230.1 -180.9,-233.1 -183.9,-235.5 -187.3,-237.4 -191,-238.5 -194.8,-238.8 -198.7,-238.5 -202.4,-237.4 -205.8,-235.5 -208.8,-233.1 -211.2,-230.1 -213,-226.7 -214.1,-223 -214.5,-219.2 -214.1,-215.3 -213,-211.6 -211.2,-208.2 -208.8,-205.2 -205.8,-202.8 -202.4,-201 -198.7,-199.9 -194.8,-199.5 -191,-199.9 -187.3,-201 -183.9,-202.8 -180.9,-205.2 -178.5,-208.2 -176.7,-211.6 -175.5,-215.3
  Board Outline Layer region: -175.2,-219.2 -175.5,-223 -176.7,-226.7 -178.5,-230.1 -180.9,-233.1 -183.9,-235.5 -187.3,-237.4 -191,-238.5 -194.8,-238.8 -198.7,-238.5 -202.4,-237.4 -205.8,-235.5 -208.8,-233.1 -211.2,-230.1 -213,-226.7 -214.1,-223 -214.5,-219.2 -214.1,-215.3 -213,-211.6 -211.2,-208.2 -208.8,-205.2 -205.8,-202.8 -202.4,-201 -198.7,-199.9 -194.8,-199.5 -191,-199.9 -187.3,-201 -183.9,-202.8 -180.9,-205.2 -178.5,-208.2 -176.7,-211.6 -175.5,-215.3
  Board Outline Layer region: 139.8,-219.2 139.4,-223 138.3,-226.7 136.5,-230.1 134,-233.1 131.1,-235.5 127.7,-237.4 124,-238.5 120.1,-238.8 116.3,-238.5 112.6,-237.4 109.2,-235.5 106.2,-233.1 103.8,-230.1 101.9,-226.7 100.8,-223 100.4,-219.2 100.8,-215.3 101.9,-211.6 103.8,-208.2 106.2,-205.2 109.2,-202.8 112.6,-201 116.3,-199.9 120.1,-199.5 124,-199.9 127.7,-201 131.1,-202.8 134,-205.2 136.5,-208.2 138.3,-211.6 139.4,-215.3
  Board Outline Layer region: 139.8,-219.2 139.4,-223 138.3,-226.7 136.5,-230.1 134,-233.1 131.1,-235.5 127.7,-237.4 124,-238.5 120.1,-238.8 116.3,-238.5 112.6,-237.4 109.2,-235.5 106.2,-233.1 103.8,-230.1 101.9,-226.7 100.8,-223 100.4,-219.2 100.8,-215.3 101.9,-211.6 103.8,-208.2 106.2,-205.2 109.2,-202.8 112.6,-201 116.3,-199.9 120.1,-199.5 124,-199.9 127.7,-201 131.1,-202.8 134,-205.2 136.5,-208.2 138.3,-211.6 139.4,-215.3
  Multi-Layer board cut-out: -175.2,-219.2 -175.5,-223 -176.7,-226.7 -178.5,-230.1 -180.9,-233.1 -183.9,-235.5 -187.3,-237.4 -191,-238.5 -194.8,-238.8 -198.7,-238.5 -202.4,-237.4 -205.8,-235.5 -208.8,-233.1 -211.2,-230.1 -213,-226.7 -214.1,-223 -214.5,-219.2 -214.1,-215.3 -213,-211.6 -211.2,-208.2 -208.8,-205.2 -205.8,-202.8 -202.4,-201 -198.7,-199.9 -194.8,-199.5 -191,-199.9 -187.3,-201 -183.9,-202.8 -180.9,-205.2 -178.5,-208.2 -176.7,-211.6 -175.5,-215.3
  Multi-Layer board cut-out: 139.8,-219.2 139.4,-223 138.3,-226.7 136.5,-230.1 134,-233.1 131.1,-235.5 127.7,-237.4 124,-238.5 120.1,-238.8 116.3,-238.5 112.6,-237.4 109.2,-235.5 106.2,-233.1 103.8,-230.1 101.9,-226.7 100.8,-223 100.4,-219.2 100.8,-215.3 101.9,-211.6 103.8,-208.2 106.2,-205.2 109.2,-202.8 112.6,-201 116.3,-199.9 120.1,-199.5 124,-199.9 127.7,-201 131.1,-202.8 134,-205.2 136.5,-208.2 138.3,-211.6 139.4,-215.3
  silkscreen extent -290,-377 290,134
USB-C_SMD-TYPE-C-31-M-12_1 [mil]
  oval 47.2x78.7 hole 31.5 slot 59.1 at 90 deg paste+0 mask+2: 1(170.3,67.2) 4(-170.3,67.2)
  oval 47.2x70.9 hole 31.5 slot 47.2 at 90 deg paste+0 mask+2: 2(170.3,-97.4) 3(-170.3,-97.4)
  round 11.8 smd: A1B12(-126,97.4) A4B9(-94.5,97.4)
  rect 11.8x51.2 smd paste-3937 mask+2: A5(-49.2,97.4) A6(-9.8,97.4) A7(9.8,97.4) A8(49.2,97.4) B5(68.9,97.4) B6(29.5,97.4) B7(-29.5,97.4) B8(-68.9,97.4)
  rect 23.6x51.2 smd paste-3937 mask+2: B1A12(126,97.4) B4A9(94.5,97.4)
  Top Layer region: -114.2,71.8 -114.2,123 -126,123 -126,123 -137.8,123 -137.8,71.8 -126,71.8 -126,71.8
  Top Layer region: -82.7,71.8 -82.7,123 -94.5,123 -94.5,123 -106.3,123 -106.3,71.8 -94.5,71.8 -94.5,71.8
  Board Outline Layer lines w0.1: 126,47.5 125.6,44.5 124.5,41.8 122.8,39.4 120.5,37.5 117.8,36.2 114.9,35.7 112,35.9 109.1,36.8 106.6,38.4 104.6,40.5 103.2,43.1 102.5,46 102.5,49 103.2,51.8 104.6,54.4 106.6,56.6 109.1,58.2 112,59.1 114.9,59.3 117.8,58.7 120.5,57.4 122.8,55.6 124.5,53.2 125.6,50.4 126,47.5 ; -102.4,47.5 -102.7,44.5 -103.8,41.8 -105.6,39.4 -107.8,37.5 -110.5,36.2 -113.4,35.7 -116.4,35.9 -119.2,36.8 -121.7,38.4 -123.7,40.5 -125.2,43.1 -125.9,46 -125.9,49 -125.2,51.8 -123.7,54.4 -121.7,56.6 -119.2,58.2 -116.4,59.1 -113.4,59.3 -110.5,58.7 -107.8,57.4 -105.6,55.6 -103.8,53.2 -102.7,50.4 -102.4,47.5
  Board Outline Layer region: -102.4,47.5 -102.7,44.5 -103.8,41.8 -105.6,39.4 -107.8,37.5 -110.5,36.2 -113.4,35.7 -116.4,35.9 -119.2,36.8 -121.7,38.4 -123.7,40.5 -125.2,43.1 -125.9,46 -125.9,49 -125.2,51.8 -123.7,54.4 -121.7,56.6 -119.2,58.2 -116.4,59.1 -113.4,59.3 -110.5,58.7 -107.8,57.4 -105.6,55.6 -103.8,53.2 -102.7,50.4
  Board Outline Layer region: -102.4,47.5 -102.7,44.5 -103.8,41.8 -105.6,39.4 -107.8,37.5 -110.5,36.2 -113.4,35.7 -116.4,35.9 -119.2,36.8 -121.7,38.4 -123.7,40.5 -125.2,43.1 -125.9,46 -125.9,49 -125.2,51.8 -123.7,54.4 -121.7,56.6 -119.2,58.2 -116.4,59.1 -113.4,59.3 -110.5,58.7 -107.8,57.4 -105.6,55.6 -103.8,53.2 -102.7,50.4
  Board Outline Layer region: 126,47.5 125.6,44.5 124.5,41.8 122.8,39.4 120.5,37.5 117.8,36.2 114.9,35.7 112,35.9 109.1,36.8 106.6,38.4 104.6,40.5 103.2,43.1 102.5,46 102.5,49 103.2,51.8 104.6,54.4 106.6,56.6 109.1,58.2 112,59.1 114.9,59.3 117.8,58.7 120.5,57.4 122.8,55.6 124.5,53.2 125.6,50.4
  Board Outline Layer region: 126,47.5 125.6,44.5 124.5,41.8 122.8,39.4 120.5,37.5 117.8,36.2 114.9,35.7 112,35.9 109.1,36.8 106.6,38.4 104.6,40.5 103.2,43.1 102.5,46 102.5,49 103.2,51.8 104.6,54.4 106.6,56.6 109.1,58.2 112,59.1 114.9,59.3 117.8,58.7 120.5,57.4 122.8,55.6 124.5,53.2 125.6,50.4
  Multi-Layer board cut-out: -102.4,47.5 -102.7,44.5 -103.8,41.8 -105.6,39.4 -107.8,37.5 -110.5,36.2 -113.4,35.7 -116.4,35.9 -119.2,36.8 -121.7,38.4 -123.7,40.5 -125.2,43.1 -125.9,46 -125.9,49 -125.2,51.8 -123.7,54.4 -121.7,56.6 -119.2,58.2 -116.4,59.1 -113.4,59.3 -110.5,58.7 -107.8,57.4 -105.6,55.6 -103.8,53.2 -102.7,50.4
  Multi-Layer board cut-out: 126,47.5 125.6,44.5 124.5,41.8 122.8,39.4 120.5,37.5 117.8,36.2 114.9,35.7 112,35.9 109.1,36.8 106.6,38.4 104.6,40.5 103.2,43.1 102.5,46 102.5,49 103.2,51.8 104.6,54.4 106.6,56.6 109.1,58.2 112,59.1 114.9,59.3 117.8,58.7 120.5,57.4 122.8,55.6 124.5,53.2 125.6,50.4
  silkscreen extent -176,-201 176,19
USON-8_L3.0-W2.0-P0.50-BL-EP [mil]
  rect 11x23.6 smd: 1(-29.5,-59.3) 2(-9.8,-59.3) 3(9.8,-59.3) 4(29.5,-59.3) 5(29.5,59.4) 6(9.8,59.4) 7(-9.8,59.4) 8(-29.5,59.4)
  rect 66.9x11.8 smd: 9(0,0)
  silkscreen extent -42,-84 42,62

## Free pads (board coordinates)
  round 122 hole 118.1: 1(3378.7,5721.5) 2(6098.7,5726.5) 3(6093.7,3866.5) 4(3368.7,3871.5)

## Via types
v1: diameter 24, hole 12, Top Layer to Bottom Layer, tented both sides, 260 vias

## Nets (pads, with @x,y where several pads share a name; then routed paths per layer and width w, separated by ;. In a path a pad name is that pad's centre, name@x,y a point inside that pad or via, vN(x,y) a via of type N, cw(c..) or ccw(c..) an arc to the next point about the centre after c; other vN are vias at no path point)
$1N5: R17.1 U1.35 U16.1 | length 1407
  Top Layer w7.8: U1.35@4821.9,5162.4 4844.9,5162.4 4874.9,5192.4 4904.9,5192.4 4924.9,5212.4 5048.5,5212.4 R17.1@5050.1,5214
  Top Layer w10: 4934.9,5212.4 4924.9,5222.4 4924.9,5642.4 v1(4974.9,5692.4) ; v1(5014.9,6202.4) U16.1@5014.9,6320.1
  Inner1 w10: v1(4974.9,5692.4) 4964.9,5702.4 4964.9,6152.4 v1(5014.9,6202.4)
$1N58: U1.75 U6.1 | length 697.8
  Top Layer w7.8: v1(4247.6,4441.5) 4247.6,4413.6 U6.1@4249.7,4411.5 ; v1(4318.5,4750.6) 4318.5,4850.6 4368.5,4900.6 4368.5,4970.6 4418.5,5020.6 U1.75@4435.5,5020.6
  Inner1 w7.8: v1(4247.6,4441.5) 4247.6,4679.7 v1(4318.5,4750.6)
$1N61: U1.74 U6.2 U7.2 | length 1756.8
  Top Layer w7.8: U6.2@4249.7,4361.5 4265.5,4361.5 4305.5,4401.5 4305.5,4478 v1(4298.4,4485.1) ; U7.2@4293.5,5745.8 4295.5,5743.9 v1(4295.5,5716.4) ; v1(4295.5,4926.4) 4295.5,4996.4 4335.5,5036.4 U1.74@4435.5,5036.4
  Inner2 w7.8: v1(4279.2,4456.2) 4298.4,4475.4 v1(4298.4,4485.1) ; v1(4295.5,4926.4) 4305.5,4936.4 4305.5,5706.4 v1(4295.5,5716.4)
  Bottom Layer w7.8: v1(4295.5,4926.4) 4295.5,4916.4 4255.5,4876.4 4255.5,4481.5 4294.9,4481.5 v1(4298.4,4485.1)
$1N63: U1.73 U6.3 U7.3 | length 1744
  Top Layer w7.8: v1(4199.7,4386.3) 4189.7,4376.3 4189.7,4356.3 4234.6,4311.5 U6.3@4249.7,4311.5 ; v1(4255.5,5012.1) 4315.5,5072.1 4335.5,5072.1 ; v1(4273.9,5203.7) 4273.9,5133.7 4355.5,5052.1 U1.73@4435.5,5052.1 ; U7.3@4273.9,5745.8 v1(4273.9,5771.7)
  Inner1 w7.8: v1(4199.7,4386.3) 4199.7,4656.3 4255.5,4712.1 4255.5,4862.1 4235.5,4882.1 4235.5,4992.1 v1(4255.5,5012.1)
  Inner2 w7.8: v1(4273.9,5203.7) 4271.8,5205.8 4271.8,5769.6 v1(4273.9,5771.7)
$1N65: U1.72 U6.5 U7.5 | length 1729.9
  Top Layer w7.8: v1(4245.5,5357.9) 4245.5,5618.5 U7.5@4254.2,5627.1 ; v1(4355.5,5087.9) 4375.5,5067.9 U1.72@4435.5,5067.9 ; v1(4375.5,4557.9) 4375.5,4397.9 4505.5,4267.9 4521.3,4267.9 U6.5@4527.7,4261.5
  Inner1 w7.8: v1(4255.5,5047.9) 4325.5,4977.9 4325.5,4827.9 4355.5,4797.9 4355.5,4577.9 v1(4375.5,4557.9)
  Bottom Layer w7.8: v1(4245.5,5357.9) 4245.5,5197.9 v1(4355.5,5087.9) ; v1(4255.5,5047.9) 4235.5,5067.9 4235.5,5117.9 4275.5,5157.9 4285.5,5157.9
$1N67: U1.71 U6.6 U7.6 | length 1555.6
  Top Layer w7.8: U7.6@4273.9,5627.1 4273.9,5235.2 4305.5,5203.6 4305.5,5173.6 4345.5,5133.6 4355.5,5133.6 4405.5,5083.6 U1.71@4435.5,5083.6 ; v1(4355.5,5123.6) v1@4365.5,5123.6 ; v1(4435.5,4443.6) 4435.5,4383.6 4505.5,4313.6 4525.6,4313.6 U6.6@4527.7,4311.5
  Inner1 w7.8: v1(4355.5,5123.6) 4425.5,5053.6 4425.5,4943.6 4405.5,4923.6 v1(4405.5,4723.6)
  Bottom Layer w7.8: v1(4405.5,4723.6) 4435.5,4693.6 v1(4435.5,4443.6)
$1N69: U1.70 U6.7 U7.7 | length 1603.8
  Top Layer w7.8: U7.7@4293.5,5627.1 4293.5,5559.3 4328.5,5524.3 4328.5,5189.4 4418.5,5099.4 U1.70@4435.5,5099.4 4415.5,5099.4 v1(4355.5,5159.4) ; v1(4405.5,4559.4) 4465.5,4499.4 4465.5,4409.4 4513.4,4361.5 U6.7@4527.7,4361.5
  Inner1 w7.8: v1(4355.5,5159.4) 4325.5,5129.4 4325.5,5079.4 4375.5,5029.4 4375.5,4589.4 v1(4405.5,4559.4)
$1N76: U1.66 U2.4 U3.7 USBC1.A7 | length 3133.8
  Top Layer w7.1: U3.7@5359.2,4169.7 5359.2,4156 5375.5,4139.7 5399.2,4139.7 v1(5415.5,4156)
  Top Layer w7.8: U1.66@4435.5,5162.4 4455.5,5162.4 4465.5,5152.4 v1(4475.5,5152.4) ; v1(4635.5,6092.4) 4648.9,6105.7 USBC1.A7@4648.9,6164.1 ; v1(5325.5,5032.4) 5365.5,5032.4 5385.5,5012.4 5385.5,4993.4 U2.4@5389.3,4989.6
  Inner1 w7.1: v1(5325.5,5032.4) 5345.5,5012.4 5345.5,4262.4 5415.5,4192.4 v1(5415.5,4156)
  Inner2 w7.8: v1(4475.5,5152.4) 4475.5,5312.4 4575.5,5412.4 4575.5,5492.4 4555.5,5512.4 4555.5,6012.4 v1(4635.5,6092.4)
  Bottom Layer w7.8: v1(4475.5,5152.4) 4495.5,5152.4 4545.5,5102.4 5225.5,5102.4 5295.5,5032.4 v1(5325.5,5032.4)
$1N77: L1.1 U1.63 | length 917.5
  Top Layer w7.8: L1.1@4303.7,6036.3 4435.5,5904.5 v1(4435.5,5750.2) ; v1(4405.5,5260.2) 4405.5,5220.2 4415.5,5210.2 4434.9,5210.2 U1.63@4435.5,5209.6
  Bottom Layer w7.8: v1(4405.5,5260.2) 4435.5,5290.2 v1(4435.5,5750.2)
$1N84: H1.1 U1.77 | length 1125.4
  Top Layer w7.8: v1(4398.5,4969.1) 4418.5,4989.1 U1.77@4435.5,4989.1
  Inner2 w7.8: v1(4398.5,4969.1) 4448.5,5019.1 4448.5,5309.1 4508.5,5369.1 4508.5,5996.3 H1.1@4513.7,6001.5
$1N85: H1.2 U1.78 | length 1111.9
  Top Layer w7.8: U1.78@4435.5,4973.4 4452.5,4973.4 v1(4502.5,5023.4)
  Inner2 w7.8: v1(4502.5,5023.4) 4613.7,5134.6 H1.2@4613.7,6001.5
$1N86: H1.3 U1.79 | length 1719.7
  Top Layer w7.8: U1.79@4435.5,4957.6 v1(4472.5,4957.6)
  Inner1 w7.8: v1(4262.5,5107.6) 4262.5,5157.6 4382.5,5277.6 v1(4382.5,5507.6)
  Inner2 w7.8: v1(4382.5,5507.6) 4392.5,5517.6 4392.5,5757.6 4352.5,5797.6 4352.5,5937.6 4532.5,6117.6 4642.5,6117.6 4713.7,6046.4 H1.3@4713.7,6001.5
  Bottom Layer w7.8: v1(4262.5,5107.6) 4302.5,5107.6 4452.5,4957.6 v1(4472.5,4957.6)
$1N87: H1.4 U1.80 | length 1273.8
  Top Layer w7.8: v1(4435.5,4921.9) U1.80@4435.5,4941.9
  Inner1 w7.8: v1(4435.5,4921.9) 4445.5,4931.9 4445.5,5001.9 4635.5,5191.9 4635.5,5261.9 4665.5,5291.9 4695.5,5291.9 4805.5,5401.9 4805.5,5993.3 H1.4@4813.7,6001.5
$1N88: H1.5 U1.1 | length 1772.7
  Top Layer w7.8: v1(4349.1,4841.3) 4406.1,4898.3 U1.1@4479.1,4898.3
  Inner1 w7.8: v1(4349.1,4841.3) v1(4349.1,5011.3)
  Inner2 w7.8: v1(4349.1,5011.3) 4379.1,5041.3 4379.1,5458.8 4413.5,5493.2 4413.5,5851.3 v1(4403.5,5861.3)
  Bottom Layer w7.8: v1(4403.5,5861.3) 4773.5,5861.3 H1.5@4913.7,6001.5
$1N89: H1.6 U1.2 | length 1392.1
  Top Layer w7.8: U1.2@4494.8,4898.3 4494.8,4881.3 v1(4514.8,4861.3)
  Inner1 w7.8: v1(4514.8,4861.3) 4554.8,4901.3 4554.8,4981.3 5003.8,5430.3 5003.8,5991.6 H1.6@5013.7,6001.5
$1N90: H1.7 U1.3 | length 1459.3
  Top Layer w7.8: U1.3@4510.6,4898.3 4510.6,4928.3 v1(4520.6,4938.3)
  Inner2 w7.8: v1(4520.6,4938.3) 4520.6,4948.3 4630.6,5058.3 4630.6,5258.3 4680.6,5308.3 4720.6,5308.3 4780.6,5368.3 4780.6,5418.3 v1(4680.6,5518.3)
  Bottom Layer w7.8: v1(4680.6,5518.3) 5113.7,5951.4 H1.7@5113.7,6001.5
$1N91: H1.8 U1.4 | length 1761.1
  Top Layer w7.8: U1.4@4526.3,4898.3 4526.3,4881.3 v1(4546.3,4861.3)
  Bottom Layer w7.8: v1(4546.3,4861.3) 4546.3,5011.3 4506.3,5051.3 4466.3,5051.3 4376.3,5141.3 4376.3,5151.3 4506.3,5281.3 4506.3,5344.1 4656.3,5494.1 4656.3,5574.1 5066.3,5984.1 5066.3,6024.1 5086.3,6044.1 5171.1,6044.1 H1.8@5213.7,6001.5
$1N92: H1.9 U1.6 | length 1416.3
  Top Layer w7.8: U1.6@4557.8,4898.3 4557.8,4915.3 v1(4587.8,4945.3)
  Inner1 w7.8: v1(4587.8,4945.3) 5313.7,5671.1 H1.9@5313.7,6001.5
$1N93: H1.10 U1.7 | length 1662.8
  Top Layer w7.8: v1(4543.6,4831.3) 4553.6,4831.3 4573.6,4851.3 U1.7@4573.6,4898.3
  Inner1 w7.8: v1(4543.6,4831.3) 4553.6,4831.3 4623.6,4901.3 4623.6,4931.3 4823.6,5131.3 4893.6,5131.3 5413.7,5651.4 H1.10@5413.7,6001.5
$1N95: H1.12 U1.9 | length 1630.1
  Top Layer w7.8: U1.9@4605.1,4898.3 4605.1,4881.3 v1(4625.1,4861.3)
  Inner1 w7.8: v1(4625.1,4861.3) 4705.1,4941.3 4705.1,4981.3 4835.1,5111.3 4895.1,5111.3 5525.1,5741.3 v1(5525.1,5901.3)
  Bottom Layer w7.8: v1(5525.1,5901.3) 5525.1,5912.9 H1.12@5613.7,6001.5
$1N101: CARD1.5 U1.16 | length 1351.6
  Top Layer w7.8: U1.16@4715.3,4898.2 4716,4897.5 v1(4716,4835.7) ; v1(5720.2,4891.4) 5811.5,4891.4 5859.6,4843.3 ; 5861.5,4841.4 5859.6,4843.3 ; CARD1.5@5909.7,4843.3 5859.6,4843.3
  Inner1 w7.8: v1@4715.3,4842.1 4716,4841.4 v1(4716,4835.7)
  Bottom Layer w7.8: v1@4720.2,4831.4 v1(4716,4835.7) 4836,4835.7 4880.2,4791.4 5060.2,4791.4 5160.2,4891.4 v1(5720.2,4891.4)
$1N102: CARD1.2 U1.17 | length 1543.6
  Top Layer w7.8: U1.17@4731.1,4898.3 4731.1,4858.3 4758,4831.4 v1(4758,4761.4) ; v1(5790.2,4991.4) 5808.3,4973.2 ; 5810.2,4971.4 5808.3,4973.2 ; CARD1.2@5909.7,4973.2 5808.3,4973.2
  Inner1 w7.8: v1(4758,4761.4) 4758,4771.4 4832.3,4845.7 4867,4845.7 4932.7,4911.4 5100.2,4911.4 5340.2,5151.4 5410.2,5151.4 5570.2,4991.4 v1(5790.2,4991.4)
$1N103: CARD1.7 U1.18 | length 1376.8
  Top Layer w7.8: U1.18@4746.8,4898.3 4746.8,4918.3 4750.2,4921.7 4793.4,4921.7 4830.2,4884.8 v1(4830.2,4804.8) ; v1(5740.2,4864.8) 5848.3,4756.7 ; 5850.2,4754.8 5848.3,4756.7 ; CARD1.7@5909.7,4756.7 5848.3,4756.7
  Bottom Layer w7.8: v1(4830.2,4804.8) 4860.2,4774.8 5070.2,4774.8 5160.2,4864.8 v1(5740.2,4864.8)
$1N104: CARD1.1 U1.19 | length 1243.7
  Top Layer w7.8: U1.19@4762.6,4898.3 4763.8,4897 v1(4763.8,4858.3) ; v1(5720.2,4954.7) 5780.2,5014.7 CARD1.1@5902.2,5014.7
  Bottom Layer w7.8: v1(4763.8,4858.3) 5103.8,4858.3 5160.2,4914.7 5680.2,4914.7 v1(5720.2,4954.7)
$1N105: CARD1.9 R6.1 U1.20 | length 1974.2
  Top Layer w7.8: U1.20@4778.3,4898.3 4788.4,4888.2 v1(4788.4,4768.2)
  Top Layer w10: R6.1@5138.7,4109.4 5147.5,4118.2 v1(5249.1,4118.2) ; v1(5789.1,4648.2) 5809.1,4668.2 CARD1.9@5902.2,4668.2
  Bottom Layer w7.8: v1(4788.4,4768.2) 4808.4,4768.2 4838.4,4738.2 4958.4,4738.2 5409.1,4287.5 5409.1,4268.2
  Bottom Layer w10: v1(5249.1,4118.2) 5329.1,4198.2 5329.1,4208.2 5349.1,4228.2 5369.1,4228.2 v1(5789.1,4648.2)
$1N107: U1.22 U23.1 | length 1420.4
  Top Layer w7.8: U1.22@4821.9,4957.6 4848.9,4957.6 v1(4858.9,4947.6)
  Inner1 w7.8: U23.1@3848.7,4113.1 4024.3,4113.1 4738.9,4827.6 4738.9,4867.6 4818.9,4947.6 v1(4858.9,4947.6)
$1N110: U1.21 U19.1 | length 973.2
  Top Layer w7.8: U1.21@4821.9,4941.9 4881.9,4881.9 v1(4881.9,4821.9)
  Inner2 w7.8: U19.1@4733.7,4054.9 4733.7,4263.7 4851.9,4381.9 4851.9,4791.9 v1(4881.9,4821.9)
$1N118: U1.23 U24.1 | length 1663.8
  Top Layer w7.8: v1(4734.9,4943.4) 4764.9,4943.4 4794.9,4973.4 U1.23@4821.9,4973.4
  Inner2 w7.8: U24.1@3563.7,4113.1 4054,4603.4 4364.9,4603.4 v1(4574.9,4813.4)
  Bottom Layer w7.8: v1(4574.9,4813.4) 4574.9,4883.4 4644.9,4953.4 4724.9,4953.4 v1(4734.9,4943.4)
$1N119: U1.25 U25.1 | length 1821.1
  Top Layer w7.8: v1(4764.9,4974.9) 4794.9,5004.9 U1.25@4821.9,5004.9
  Inner2 w7.8: U25.1@3160.3,4676.5 3208.7,4724.9 4344.9,4724.9 4504.9,4884.9 4714.9,4884.9 4764.9,4934.9 v1(4764.9,4974.9)
$1N120: U1.26 U26.1 | length 1715.3
  Top Layer w7.8: U1.26@4821.9,5020.6 v1(4858.9,5020.6)
  Inner2 w7.8: U26.1@4208.7,4049.9 4248,4010.6 4748.9,4010.6 4778.9,4040.6 4778.9,4230.6 4908.9,4360.6 4908.9,4780.6 4938.9,4810.6 4938.9,4930.6 4858.9,5010.6 v1(4858.9,5020.6)
$1N122: U1.28 U28.1 | length 1927.6
  Top Layer w7.8: U1.28@4821.9,5052.1 4858.9,5052.1 4888.9,5022.1 v1(4888.9,5012.1)
  Inner1 w7.8: U28.1@3683.7,3673.1 3728.9,3718.3 3728.9,3782.1 4888.9,4942.1 v1(4888.9,5012.1)
$1N124: U1.27 U27.1 | length 1779.6
  Top Layer w7.8: v1(4734.9,4976.4) 4794.9,5036.4 U1.27@4821.9,5036.4
  Inner2 w7.8: U27.1@3160.3,4931.5 3210.3,4981.5 3370,4981.5 3430,4921.5 3915.1,4921.5 3945.1,4891.5 4440,4891.5 4460,4911.5 4590,4911.5 4654.9,4976.4 v1(4734.9,4976.4)
$1N128: U1.36 U29.1 | length 1554.4
  Top Layer w7.8: v1(4784.9,5178.1) U1.36@4821.9,5178.1
  Inner1 w7.8: v1(4604.9,4998.1) v1(4784.9,5178.1)
  Inner2 w7.8: U29.1@4473.7,4054.9 4473.7,4556.9 4738.9,4822.1 4738.9,4882.1 4794.9,4938.1 4794.9,4978.1 4764.9,5008.1 4614.9,5008.1 v1(4604.9,4998.1)
$1N129: U1.37 U30.1 | length 2287.3
  Top Layer w7.8: v1(4804.9,5263.8) 4794.9,5253.8 4794.9,5203.8 4804.9,5193.8 U1.37@4821.9,5193.8
  Inner1 w7.8: U30.1@3288.7,4113.1 3339.5,4163.8 4044.9,4163.8 4434.9,4553.8 4434.9,4883.8 4804.9,5253.8 v1(4804.9,5263.8)
$1N130: U1.38 U20.1 | length 1566.2
  Top Layer w7.8: U1.38@4821.9,5209.6 4888.9,5209.6 v1(4898.9,5219.6)
  Inner2 w7.8: v1(5968.9,5439.6) 6116.8,5439.6 U20.1@6223.7,5546.5
  Bottom Layer w7.8: v1(4898.9,5219.6) 4928.9,5189.6 5098.9,5189.6 5278.9,5369.6 5748.9,5369.6 5818.9,5439.6 v1(5968.9,5439.6)
$1N131: U1.39 U20.2 | length 1670.8
  Top Layer w7.8: U1.39@4821.9,5225.4 4870.4,5225.4 4908.9,5263.8 4908.9,5535.3 v1(4898.9,5545.3)
  Bottom Layer w7.8: v1(4898.9,5545.3) 5678.9,5545.3 5698.9,5565.3 5838.9,5565.3 5907.8,5496.5 6073.7,5496.5 U20.2@6123.7,5546.5
$1N132: R9.1 U1.40 | length 329.3
  Top Layer w7.8: U1.40@4821.9,5241.1 4851.9,5241.1 v1(4881.9,5271.1) ; v1(5089,5214) R9.1@5115.1,5214
  Bottom Layer w7.8: v1(4881.9,5271.1) 4939,5214 v1(5089,5214)
$1N133: LED1.2 R9.2 | length 611.3
  Top Layer w10: LED1.2@4939.2,4641.5 4939.2,4681.5 v1(4959.2,4701.5) ; v1(5099.2,4941.5) 5099.2,5164 R9.2@5115.1,5179.9
  Inner2 w10: v1(4959.2,4701.5) 4959.2,4781.5 5099.2,4921.5 v1(5099.2,4941.5)
$1N134: U1.42 U7.1 | length 808
  Top Layer w7.8: U7.1@4313.2,5745.8 4369.1,5801.7 v1(4382.6,5801.7) ; v1(4752.6,5381.7) 4762.6,5371.7 U1.42@4762.6,5284.7
  Inner1 w7.8: v1(4382.6,5801.7) 4402.6,5781.7 4472.6,5781.7 v1(4642.6,5611.7)
  Inner2 w7.8: v1(4642.6,5611.7) 4642.6,5491.7 v1(4752.6,5381.7)
$1N135: C1.1 U1.68 | length 1014
  Top Layer w7.8: U1.68@4435.5,5130.9 4465.5,5130.9 4475.5,5120.9 v1(4495.5,5120.9) ; v1(4585.5,5520.9) 4787.6,5723 C1.1@5006.1,5723
  Inner2 w7.8: v1(4495.5,5120.9) 4545.5,5170.9 4545.5,5310.9 4595.5,5360.9 4595.5,5510.9 v1(4585.5,5520.9)
$1N136: U1.43 U18.24 | length 1394.7
  Top Layer w7.8: v1(3689.5,5922) U18.24@3721.9,5922 ; v1(4646.8,5404.7) 4666.8,5404.7 4746.8,5324.7 U1.43@4746.8,5284.7
  Inner1 w7.8: v1(3689.5,5922) 4159.5,5922 4296.8,5784.7 4296.8,5774.7 4646.8,5424.7 v1(4646.8,5404.7)
$1N137: U1.44 U17.2 U18.57 | length 2729.1
  Top Layer w7.8: v1(4071.1,5781.7) 4051.1,5761.7 4051.1,5741.7 4067.6,5725.2 U18.57@4106.2,5725.2 ; v1(4541.1,5431.7) 4581.1,5431.7 4631.1,5381.7 4661.1,5381.7 4731.1,5311.7 U1.44@4731.1,5284.7 ; 4611.1,5401.7 4641.1,5431.7 v1(4671.1,5431.7) ; v1(5651.1,4701.7) 5651.1,4671.4 U17.2@5670.2,4652.2
  Inner1 w7.8: v1(4071.1,5781.7) 4081.1,5771.7 4141.1,5771.7 4191.1,5721.7 4241.1,5721.7 4531.1,5431.7 v1(4541.1,5431.7)
  Inner2 w7.8: v1(5331.1,5491.7) 5651.1,5171.7 v1(5651.1,4701.7)
  Bottom Layer w7.8: v1(4671.1,5431.7) 4731.1,5491.7 v1(5331.1,5491.7)
$1N138: U1.45 U18.58 | length 1496.1
  Top Layer w7.8: v1(4076.2,5748.6) 4102.4,5748.6 U18.58@4106.2,5744.8 ; U1.45@4715.3,5284.7 4715.3,5257.7 v1(4725.3,5247.7)
  Inner1 w7.8: v1(4725.3,5247.7) 4725.3,5297.7 4832.4,5404.8 v1(4832.4,5834.8)
  Bottom Layer w7.8: v1(4076.2,5748.6) 4162.4,5834.8 v1(4832.4,5834.8)
$1N139: U1.46 U17.3 U18.59 | length 2538.6
  Top Layer w7.8: U18.59@4106.2,5764.5 4109,5761.7 v1(4219.6,5761.7) ; v1(4679.6,5331.7) 4679.6,5321.7 4699.6,5301.7 U1.46@4699.6,5284.7 ; v1(5705.3,4651.7) 5705.3,4631.7 5715.3,4621.7 5735.3,4621.7 U17.3@5737.2,4619.8
  Inner1 w7.8: v1(4219.6,5761.7) 4239.6,5741.7 4309.6,5741.7 4559.6,5491.7 4559.6,5451.7 v1(4679.6,5331.7)
  Inner2 w7.8: v1(5299.6,5441.7) 5299.6,5341.7 5619.6,5021.7 5619.6,4701.7 5669.6,4651.7 v1(5705.3,4651.7)
  Bottom Layer w7.8: v1(4679.6,5331.7) 4679.6,5341.7 4779.6,5441.7 v1(5299.6,5441.7)
$1N142: U1.48 U15.14 | length 1062.4
  Top Layer w7.8: U15.14@3864.8,4848 3868.5,4851.7 3868.5,4861.7 3888.5,4881.7 v1(3908.1,4881.7) ; v1(4648.1,5331.7) 4668.1,5311.7 U1.48@4668.1,5284.7
  Inner1 w7.8: v1(3908.1,4881.7) 4098.1,5071.7 4258.1,5071.7 4288.1,5101.7 4288.1,5131.7 4338.1,5181.7 4468.1,5181.7 4558.1,5271.7 4588.1,5271.7 v1(4648.1,5331.7)
$1N144: U1.53 U2.10 | length 1587.6
  Top Layer w7.8: U1.53@4589.3,5284.7 v1(4589.3,5314.7) ; v1(5459.3,4941.5) 5479.3,4941.5 5519.3,4901.5 5519.3,4765.3 U2.10@5507.4,4753.4
  Bottom Layer w7.8: v1(4589.3,5314.7) 4449.3,5174.7 4449.3,5134.7 4499.3,5084.7 5149.3,5084.7 5292.5,4941.5 v1(5459.3,4941.5)
$1N152: U1.54 U31.1 | length 1247
  Top Layer w7.8: v1(4573.6,5247.7) U1.54@4573.6,5284.7
  Bottom Layer w7.8: v1(4573.6,5247.7) 4633.6,5307.7 4713.6,5307.7 4822.4,5416.5 U31.1@5713.7,5416.5
$1N156: U1.56 U32.1 | length 1910.7
  Top Layer w7.8: U1.56@4542.1,5284.7 4542.1,5247.7 v1(4572.1,5217.7)
  Bottom Layer w7.8: v1(4572.1,5217.7) 4552.1,5197.7 4552.1,5177.7 4602.1,5127.7 5102.1,5127.7 5272.1,5297.7 6174.9,5297.7 U32.1@6223.7,5346.5
$1N157: U1.57 U32.2 | length 1744.3
  Top Layer w7.8: U1.57@4526.3,5284.7 4526.3,5324.7 v1(4536.3,5334.7)
  Bottom Layer w7.8: v1(4536.3,5334.7) 4566.3,5334.7 4586.3,5354.7 4666.3,5354.7 4776.3,5464.7 6005.5,5464.7 U32.2@6123.7,5346.5
$1N158: U1.58 U32.3 | length 1716.3
  Top Layer w7.8: U1.58@4510.6,5284.7 4510.6,5247.7 4570.6,5187.7 v1(4580.6,5187.7)
  Bottom Layer w7.8: v1(4580.6,5187.7) 4600.6,5207.7 4879.4,5207.7 4919.4,5167.7 5100.6,5167.7 5270.6,5337.7 5850.6,5337.7 5910.6,5397.7 5972.5,5397.7 U32.3@6023.7,5346.5
$1N165: C5.1 U18.21 X2.4 | length 1785.4
  Top Layer w8.1: X2.4@3635.2,5253.2 3595.2,5293.2 3595.2,5904.2 3672.1,5981.1 U18.21@3721.9,5981.1
  Top Layer w10: X2.4@3635.2,5253.2 3745.2,5143.2 3825.2,5143.2 3965.2,5003.2 4148.5,5003.2 4208.5,4943.2 4208.5,4813.2 C5.1@4298.7,4723
$1N166: C4.1 U18.22 X2.2 | length 2600.1
  Top Layer w8.1: X2.2@3702.2,5339.8 3652.1,5389.9 3652.1,5921.4 3692.1,5961.4 U18.22@3721.9,5961.4
  Top Layer w10: v1(5212.1,5161.4) 5250.4,5161.4 C4.1@5261.6,5172.6
  Inner1 w10: v1(3682.1,5951.4) 4192.1,5951.4 4602.1,5541.4 v1(4782.1,5541.4)
  Inner2 w10: v1(4782.1,5541.4) 4832.1,5541.4 v1(5212.1,5161.4)
$1N185: U1.47 U14.11 | length 1102.9
  Top Layer w7.8: U1.47@4683.8,5284.7 4683.8,5267.7 4693.8,5257.7 v1(4693.8,5237.7) ; U14.11@4828.3,4386.6 4828.3,4406.6 4843.8,4422.1 v1(4873.8,4422.1)
  Inner1 w7.8: v1(4873.8,4422.1) 4933.8,4482.1 v1(4933.8,4492.1)
  Inner2 w7.8: v1(4693.8,5237.7) 4893.8,5037.7 4933.8,5037.7 4953.8,5017.7 4953.8,4797.7 4933.8,4777.7 v1(4933.8,4492.1)
$1N190: U1.52 U3.21 | length 1326.9
  Top Layer w7.1: U1.52@4605.1,5284.7 4605.1,5248.1 v1(4675.1,5178.1) ; v1(5285.1,4358.1) 5295.1,4358.1 5312,4341.2 U3.21@5312,4323.3
  Inner2 w7.1: v1(4675.1,5178.1) 4815.1,5038.1 4815.1,4888.1 4805.1,4878.1 4805.1,4798.1 4825.1,4778.1 v1(4825.1,4718.1)
  Bottom Layer w7.1: v1(4825.1,4718.1) 4895.1,4718.1 5235.1,4378.1 5265.1,4378.1 v1(5285.1,4358.1)
$1N191: U1.55 U31.2 | length 1305.3
  Top Layer w7.8: U1.55@4557.8,5284.7 4557.8,5311.7 4567.8,5321.7 4567.8,5351.7 v1(4557.8,5361.7)
  Bottom Layer w7.8: v1(4557.8,5361.7) 4712.6,5516.5 U31.2@5713.7,5516.5
$1N192: C24.1 U14.24 | length 531.5
  Top Layer w8.5: v1(4646,4616.4) C24.1@4646,4644.3 ; v1(4896,4246.4) U14.24@4896,4276.4
  Inner1 w8.5: v1(4646,4616.4) 4646,4496.4 v1(4896,4246.4)
$1N193: C23.1 U14.21 | length 247.2
  Top Layer w8.5: v1(4825.2,4474.4) 4825.2,4514.5 C23.1@4825.8,4515 ; U14.21@4845.2,4276.4 v1(4845.2,4334.4)
  Inner1 w8.5: v1(4825.2,4474.4) 4845.2,4454.4 v1(4845.2,4334.4)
